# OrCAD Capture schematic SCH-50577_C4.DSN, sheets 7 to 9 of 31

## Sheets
7 05 MIMXRT1180 Part1: size C
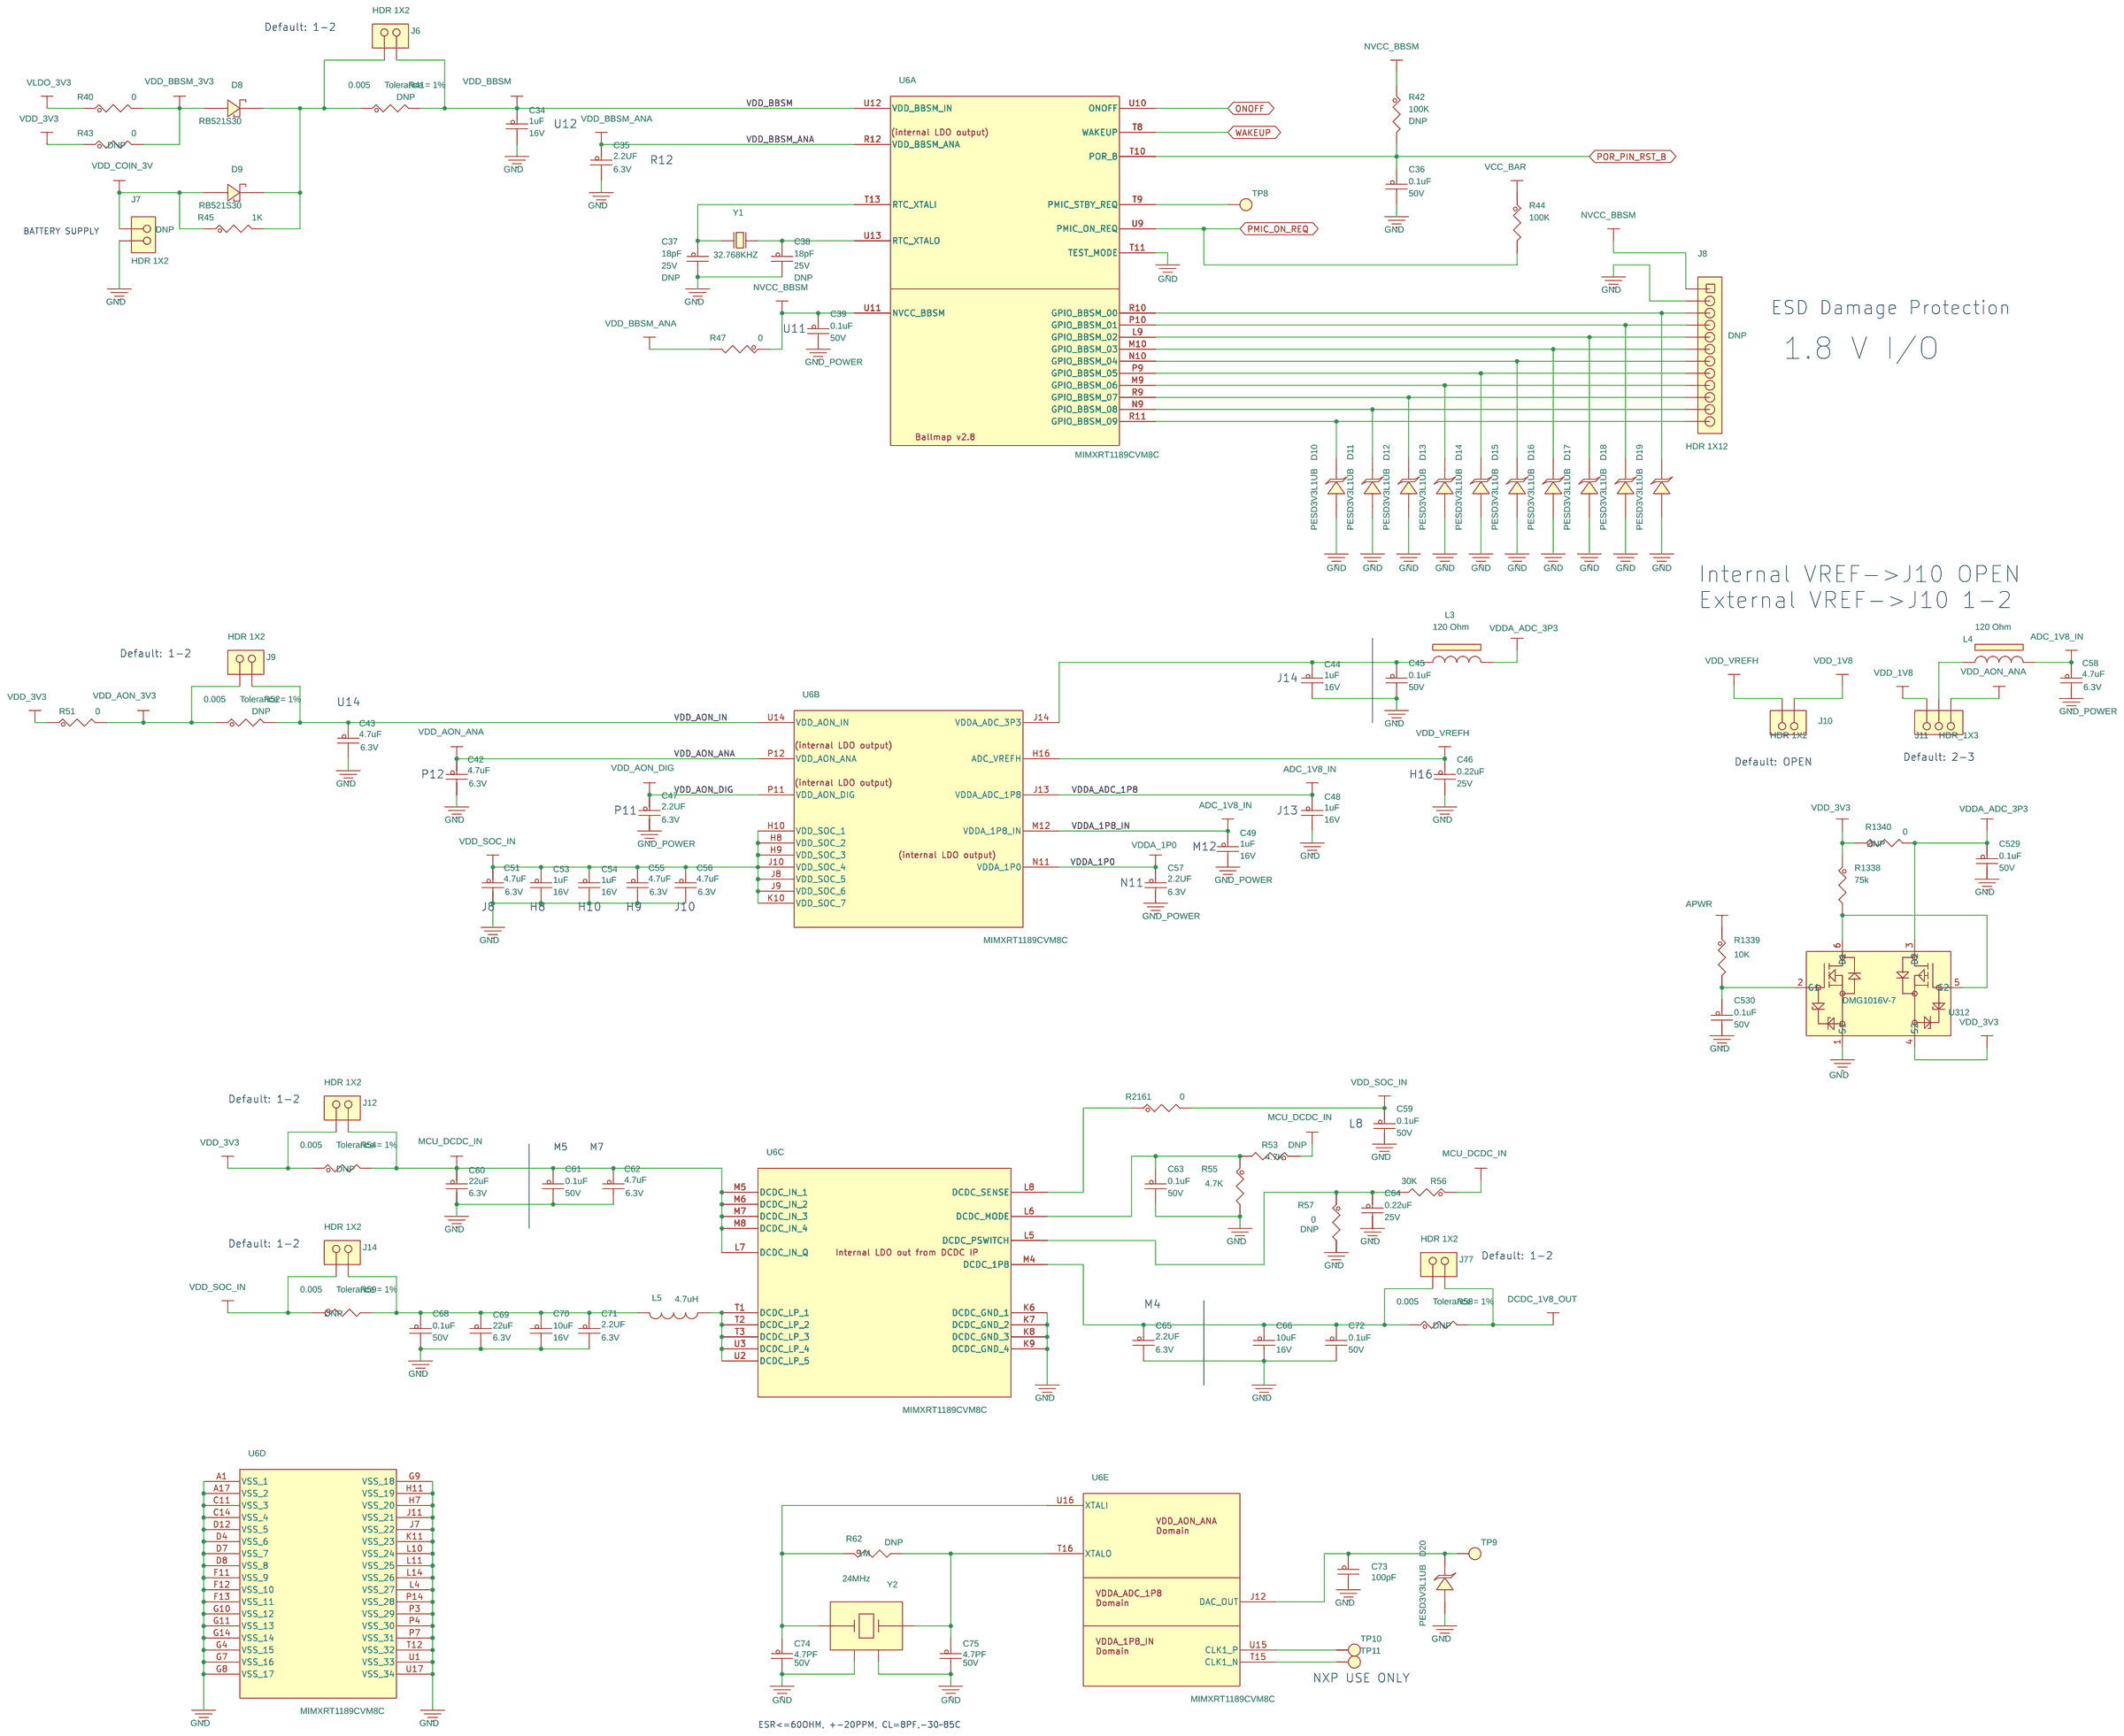
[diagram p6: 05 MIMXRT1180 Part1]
8 06 MIMXRT1180 Part2: size C
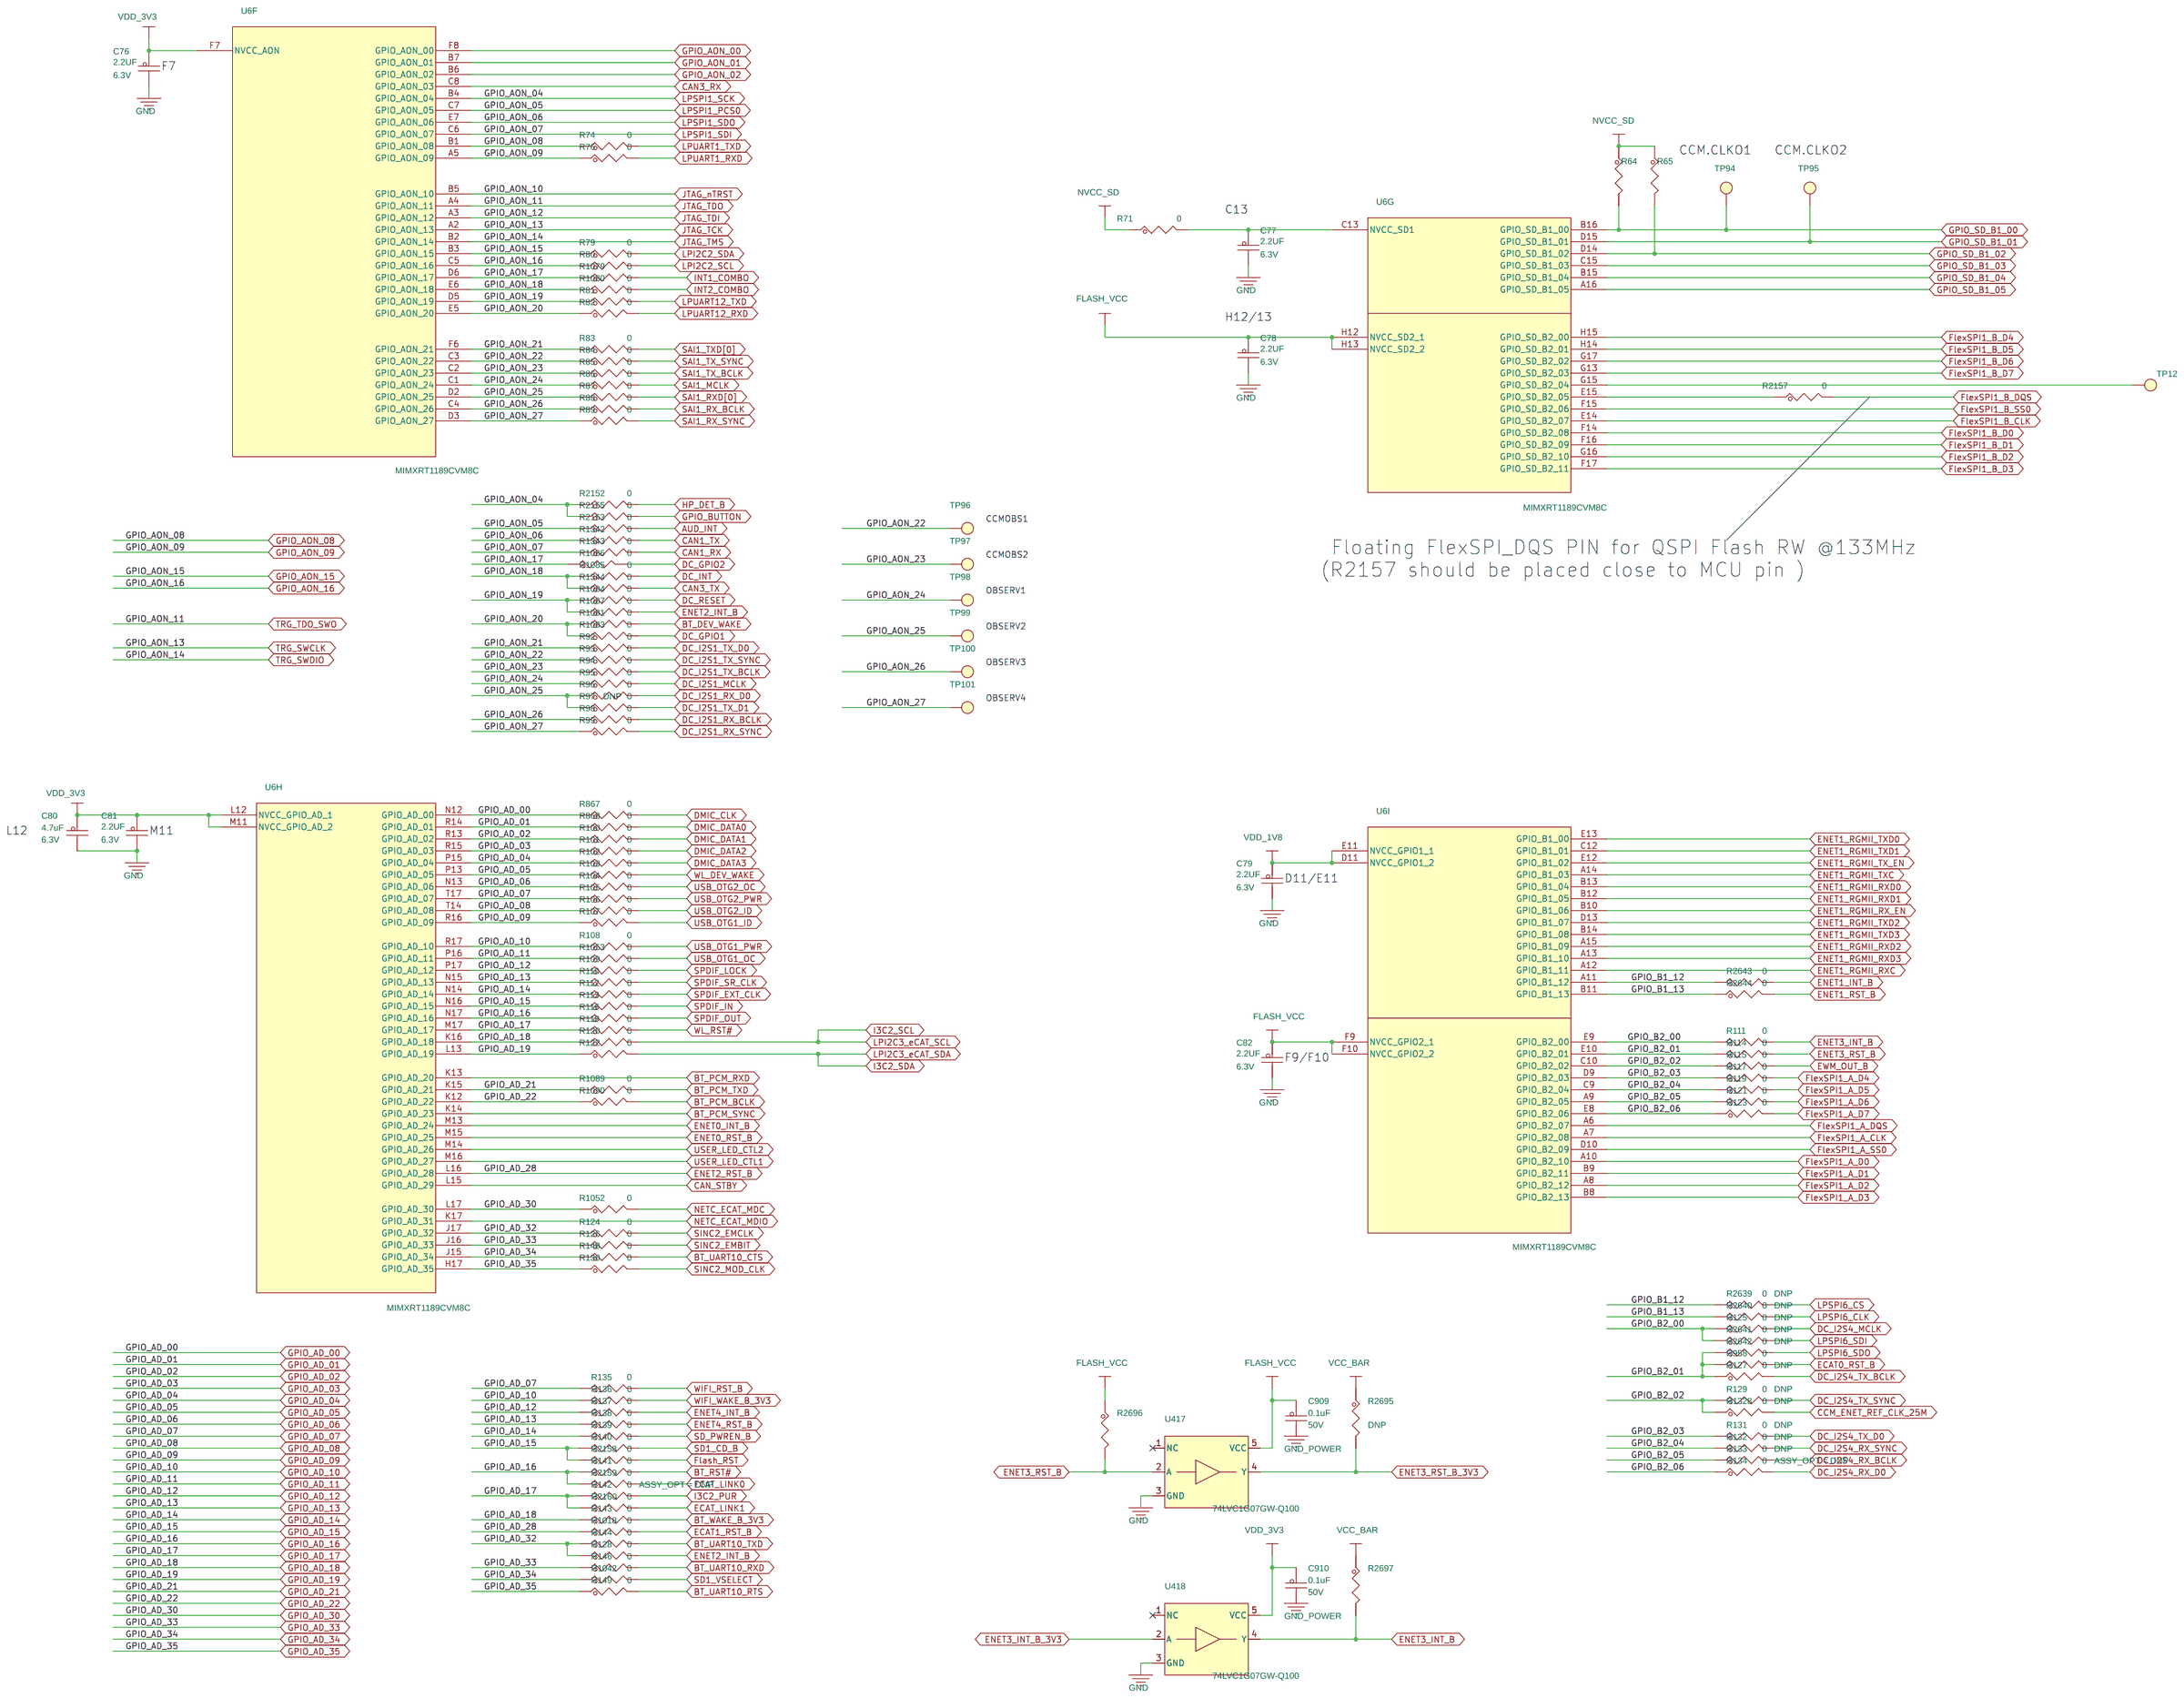
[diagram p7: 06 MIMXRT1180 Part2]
9 07 MIMXRT1180 Part3: size C
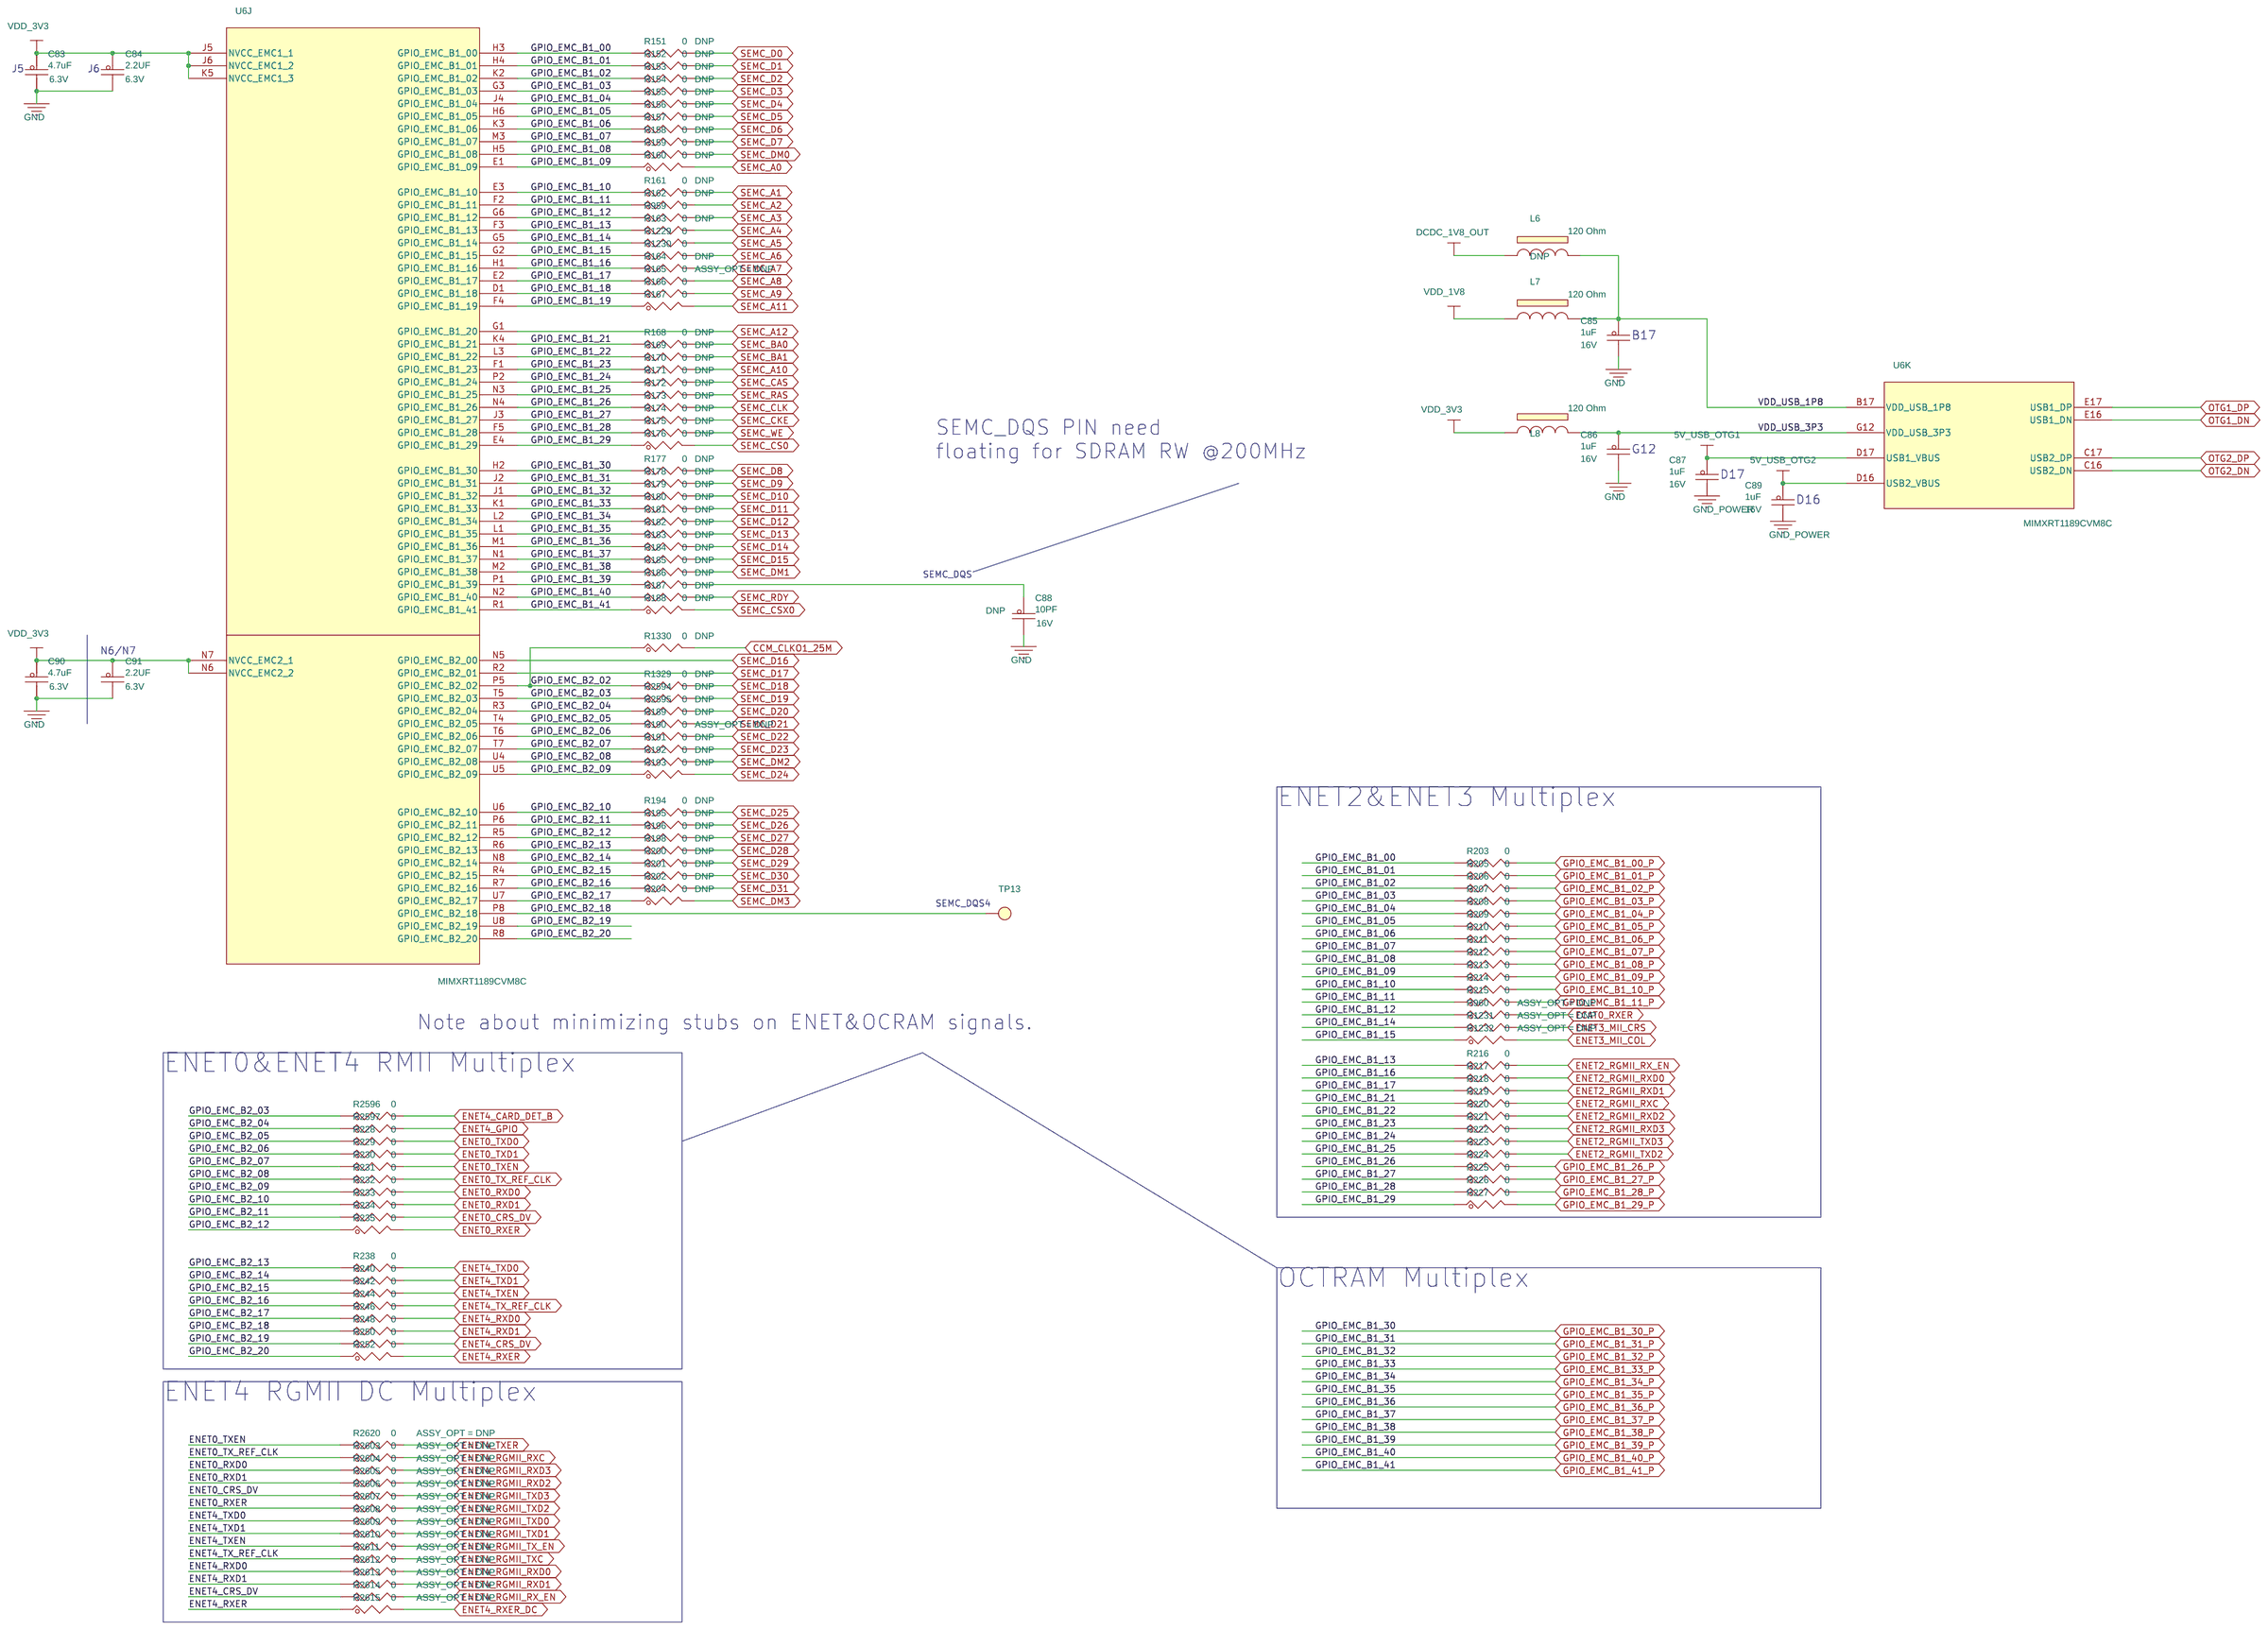
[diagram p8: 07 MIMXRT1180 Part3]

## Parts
sheet 05 MIMXRT1180 Part1
C34  1uF  [0402_CC]
C35  2.2UF  [0402_CC]
C36  0.1uF  [0402_CC]
C37  18pF  [0402_CC]
C38  18pF  [0402_CC]
C39  0.1uF  [0402_CC]
C42  4.7uF  [cc0402_tol0p15]
C43  4.7uF  [cc0402_tol0p15]
C44  1uF  [0402_CC]
C45  0.1uF  [0402_CC]
C46  0.22uF  [0402_CC]
C47  2.2UF  [0402_CC]
C48  1uF  [0402_CC]
C49  1uF  [0402_CC]
C51  4.7uF  [cc0402_tol0p15]
C53  1uF  [0402_CC]
C54  1uF  [0402_CC]
C55  4.7uF  [cc0402_tol0p15]
C56  4.7uF  [cc0402_tol0p15]
C57  2.2UF  [0402_CC]
C58  4.7uF  [cc0402_tol0p15]
C59  0.1uF  [0402_CC]
C60  22uF  [CC0603_OV]
C61  0.1uF  [0402_CC]
C62  4.7uF  [cc0402_tol0p15]
C63  0.1uF  [0402_CC]
C64  0.22uF  [0402_CC]
C65  2.2UF  [0402_CC]
C66  10uF  [CC0603_OV]
C68  0.1uF  [0402_CC]
C69  22uF  [CC0603_OV]
C70  10uF  [CC0603_OV]
C71  2.2UF  [0402_CC]
C72  0.1uF  [0402_CC]
C73  100pF  [0402_CC]
C74  4.7PF  [0402_CC]
C75  4.7PF  [0402_CC]
C529  0.1uF  [0402_CC]
C530  0.1uF  [0402_CC]
D8  RB521S30  [SOD523]
D9  RB521S30  [SOD523]
D10  PESD3V3L1UB  [sod523]
D11  PESD3V3L1UB  [sod523]
D12  PESD3V3L1UB  [sod523]
D13  PESD3V3L1UB  [sod523]
D14  PESD3V3L1UB  [sod523]
D15  PESD3V3L1UB  [sod523]
D16  PESD3V3L1UB  [sod523]
D17  PESD3V3L1UB  [sod523]
D18  PESD3V3L1UB  [sod523]
D19  PESD3V3L1UB  [sod523]
D20  PESD3V3L1UB  [sod523]
J6  HDR 1X2  [HDR102]
J7  HDR 1X2  [HDR102]
J8  HDR 1X12  [hdr112_b]
J9  HDR 1X2  [HDR102]
J10  HDR 1X2  [HDR102]
J11  HDR_1X3  [HDR103]
J12  HDR 1X2  [HDR102]
J14  HDR 1X2  [HDR102]
J77  HDR 1X2  [HDR102]
L3  120 Ohm  [0402_CC]
L4  120 Ohm  [0402_CC]
L5  4.7uH  [ind_4p2x4p2]
R40  0  [0402_CC]
R41  0.005  [RC0603_OV]
R42  100K  [0402_CC]
R43  0  [0402_CC]
R44  100K  [0402_CC]
R45  1K  [0402_CC]
R47  0  [0402_CC]
R51  0  [0402_CC]
R52  0.005  [RC0603_OV]
R53  4.7K  [0402_CC]
R54  0.005  [RC0603_OV]
R55  4.7K  [0402_CC]
R56  30K  [0402_CC]
R57  0  [0402_CC]
R58  0.005  [RC0603_OV]
R59  0.005  [RC0603_OV]
R62  1M  [0402_CC]
R1338  75k  [RC0402_25]
R1339  10K  [0402_CC]
R1340  0  [0402_CC]
R2161  0  [0402_CC]
TP8  TP_35MIL  [testpoint_35mil]
TP9  TP_35MIL  [testpoint_35mil]
TP10  TP_35MIL  [testpoint_35mil]
TP11  TP_35MIL  [testpoint_35mil]
U312  DMG1016V-7  [sot-563_6p_0p5_smt]
Y1  32.768KHZ  [XTAL2-3p2x1p5-SM]
Y2  24MHz  [xtl4_2p1x1p7mm_sm]
sheet 06 MIMXRT1180 Part2
C76  2.2UF  [0402_CC]
C77  2.2UF  [0402_CC]
C78  2.2UF  [0402_CC]
C79  2.2UF  [0402_CC]
C80  4.7uF  [cc0402_tol0p15]
C81  2.2UF  [0402_CC]
C82  2.2UF  [0402_CC]
C909  0.1uF  [0402_CC]
C910  0.1uF  [0402_CC]
R64  10K  [0402_CC]
R65  10K  [0402_CC]
R71  0  [0402_CC]
R74  0  [0402_CC]
R76  0  [0402_CC]
R79  0  [0402_CC]
R80  0  [0402_CC]
R81  0  [0402_CC]
R82  0  [0402_CC]
R83  0  [0402_CC]
R84  0  [0402_CC]
R85  0  [0402_CC]
R86  0  [0402_CC]
R87  0  [0402_CC]
R88  0  [0402_CC]
R89  0  [0402_CC]
R92  0  [0402_CC]
R93  0  [0402_CC]
R94  0  [0402_CC]
R95  0  [0402_CC]
R96  0  [0402_CC]
R97  0  [0402_CC]
R98  0  [0402_CC]
R99  0  [0402_CC]
R100  0  [0402_CC]
R101  0  [0402_CC]
R102  0  [0402_CC]
R103  0  [0402_CC]
R104  0  [0402_CC]
R105  0  [0402_CC]
R106  0  [0402_CC]
R107  0  [0402_CC]
R108  0  [0402_CC]
R109  0  [0402_CC]
R110  0  [0402_CC]
R111  0  [0402_CC]
R112  0  [0402_CC]
R113  0  [0402_CC]
R114  0  [0402_CC]
R115  0  [0402_CC]
R116  0  [0402_CC]
R117  0  [0402_CC]
R118  0  [0402_CC]
R119  0  [0402_CC]
R120  0  [0402_CC]
R121  0  [0402_CC]
R122  0  [0402_CC]
R123  0  [0402_CC]
R124  0  [0402_CC]
R125  0  [0402_CC]
R126  0  [0402_CC]
R127  0  [0402_CC]
R128  0  [0402_CC]
R129  0  [0402_CC]
R130  0  [0402_CC]
R131  0  [0402_CC]
R132  0  [0402_CC]
R133  0  [0402_CC]
R134  0  [0402_CC]
R135  0  [0402_CC]
R136  0  [0402_CC]
R137  0  [0402_CC]
R138  0  [0402_CC]
R139  0  [0402_CC]
R140  0  [0402_CC]
R141  0  [0402_CC]
R142  0  [0402_CC]
R143  0  [0402_CC]
R144  0  [0402_CC]
R146  0  [0402_CC]
R148  0  [0402_CC]
R149  0  [0402_CC]
R867  0  [0402_CC]
R868  0  [0402_CC]
R958  0  [0402_CC]
R1018  0  [0402_CC]
R1042  0  [0402_CC]
R1052  0  [0402_CC]
R1053  0  [0402_CC]
R1079  0  [0402_CC]
R1080  0  [0402_CC]
R1081  0  [0402_CC]
R1083  0  [0402_CC]
R1084  0  [0402_CC]
R1085  0  [0402_CC]
R1086  0  [0402_CC]
R1087  0  [0402_CC]
R1089  0  [0402_CC]
R1090  0  [0402_CC]
R1328  0  [0402_CC]
R1342  0  [0402_CC]
R1343  0  [0402_CC]
R1344  0  [0402_CC]
R2152  0  [0402_CC]
R2153  0  [0402_CC]
R2155  0  [0402_CC]
R2157  0  [0402_CC]
R2158  0  [0402_CC]
R2159  0  [0402_CC]
R2160  0  [0402_CC]
R2639  0  [0402_CC]
R2640  0  [0402_CC]
R2641  0  [0402_CC]
R2642  0  [0402_CC]
R2643  0  [0402_CC]
R2644  0  [0402_CC]
R2695  4.7K  [0402_CC]
R2696  10K  [0402_CC]
R2697  4.7K  [0402_CC]
TP12  TP_35MIL  [testpoint_35mil]
TP94  TP_35MIL  [testpoint_35mil]
TP95  TP_35MIL  [testpoint_35mil]
TP96  TP_35MIL  [testpoint_35mil]
TP97  TP_35MIL  [testpoint_35mil]
TP98  TP_35MIL  [testpoint_35mil]
TP99  TP_35MIL  [testpoint_35mil]
TP100  TP_35MIL  [testpoint_35mil]
TP101  TP_35MIL  [testpoint_35mil]
U417  74LVC1G07GW-Q100  [sc70-5]
U418  74LVC1G07GW-Q100  [sc70-5]
sheet 07 MIMXRT1180 Part3
C83  4.7uF  [cc0402_tol0p15]
C84  2.2UF  [0402_CC]
C85  1uF  [0402_CC]
C86  1uF  [0402_CC]
C87  1uF  [0402_CC]
C88  10PF  [0402_CC]
C89  1uF  [0402_CC]
C90  4.7uF  [cc0402_tol0p15]
C91  2.2UF  [0402_CC]
L6  120 Ohm  [0402_CC]
L7  120 Ohm  [0402_CC]
L8  120 Ohm  [0402_CC]
R151  0  [0402_CC]
R152  0  [0402_CC]
R153  0  [0402_CC]
R154  0  [0402_CC]
R155  0  [0402_CC]
R156  0  [0402_CC]
R157  0  [0402_CC]
R158  0  [0402_CC]
R159  0  [0402_CC]
R160  0  [0402_CC]
R161  0  [0402_CC]
R162  0  [0402_CC]
R163  0  [0402_CC]
R164  0  [0402_CC]
R165  0  [0402_CC]
R166  0  [0402_CC]
R167  0  [0402_CC]
R168  0  [0402_CC]
R169  0  [0402_CC]
R170  0  [0402_CC]
R171  0  [0402_CC]
R172  0  [0402_CC]
R173  0  [0402_CC]
R174  0  [0402_CC]
R175  0  [0402_CC]
R176  0  [0402_CC]
R177  0  [0402_CC]
R178  0  [0402_CC]
R179  0  [0402_CC]
R180  0  [0402_CC]
R181  0  [0402_CC]
R182  0  [0402_CC]
R183  0  [0402_CC]
R184  0  [0402_CC]
R185  0  [0402_CC]
R186  0  [0402_CC]
R187  0  [0402_CC]
R188  0  [0402_CC]
R189  0  [0402_CC]
R190  0  [0402_CC]
R191  0  [0402_CC]
R192  0  [0402_CC]
R193  0  [0402_CC]
R194  0  [0402_CC]
R195  0  [0402_CC]
R196  0  [0402_CC]
R198  0  [0402_CC]
R200  0  [0402_CC]
R201  0  [0402_CC]
R202  0  [0402_CC]
R203  0  [0402_CC]
R204  0  [0402_CC]
R205  0  [0402_CC]
R206  0  [0402_CC]
R207  0  [0402_CC]
R208  0  [0402_CC]
R209  0  [0402_CC]
R210  0  [0402_CC]
R211  0  [0402_CC]
R212  0  [0402_CC]
R213  0  [0402_CC]
R214  0  [0402_CC]
R215  0  [0402_CC]
R216  0  [0402_CC]
R217  0  [0402_CC]
R218  0  [0402_CC]
R219  0  [0402_CC]
R220  0  [0402_CC]
R221  0  [0402_CC]
R222  0  [0402_CC]
R223  0  [0402_CC]
R224  0  [0402_CC]
R225  0  [0402_CC]
R226  0  [0402_CC]
R227  0  [0402_CC]
R228  0  [0402_CC]
R229  0  [0402_CC]
R230  0  [0402_CC]
R231  0  [0402_CC]
R232  0  [0402_CC]
R233  0  [0402_CC]
R234  0  [0402_CC]
R235  0  [0402_CC]
R238  0  [0402_CC]
R240  0  [0402_CC]
R242  0  [0402_CC]
R244  0  [0402_CC]
R246  0  [0402_CC]
R248  0  [0402_CC]
R250  0  [0402_CC]
R252  0  [0402_CC]
R959  0  [0402_CC]
R960  0  [0402_CC]
R1229  0  [0402_CC]
R1230  0  [0402_CC]
R1231  0  [0402_CC]
R1232  0  [0402_CC]
R1329  0  [0402_CC]
R1330  0  [0402_CC]
R2594  0  [0402_CC]
R2595  0  [0402_CC]
R2596  0  [0402_CC]
R2597  0  [0402_CC]
R2603  0  [0402_CC]
R2604  0  [0402_CC]
R2605  0  [0402_CC]
R2606  0  [0402_CC]
R2607  0  [0402_CC]
R2608  0  [0402_CC]
R2609  0  [0402_CC]
R2610  0  [0402_CC]
R2611  0  [0402_CC]
R2612  0  [0402_CC]
R2613  0  [0402_CC]
R2614  0  [0402_CC]
R2615  0  [0402_CC]
R2620  0  [0402_CC]
TP13  TP_35MIL  [testpoint_35mil]
U6  MIMXRT1189CVM8C  [bga289_0p8_14x14_1p52mm]  (sections A,B,C,D,E,F,G,H,I,J,K)

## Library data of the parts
C34 C44 C48 C49 C53 C54 C85-C87 C89 = CAP_NP: CAP CER 1.0uF 16V 10% X6S 0402; AGILE_PN: 150-80262; CAD_APPROVED: Yes; FPLIST: CC0402_25,CC0402_HD,0402_CC,capc0402_l; HEIGHT: 0.55MM; MFG_NAME01: MURATA; MFG_PN01: GRM155C81C105KE11D; ROHS: Yes; Temp Range: -55°C to +105°C; Tolerance: 10%; VOLTAGE: 16V
C35 C47 C57 C65 C71 C76-C79 C81 C82 C84 C91 = CAP_NP: CAP CER 2.2UF 6.3V 10% X6S 0402; AGILE_PN: 150-80139; CAD_APPROVED: Yes; FPLIST: CC0402_25,CC0402_HD,0402_CC,capc0402_l; HEIGHT: 0.55MM; MFG_NAME01: MURATA; MFG_PN01: GRM155C80J225KE95D; ROHS: Yes; Temp Range: -55 to 105&#8451;; VOLTAGE: 6.3V
C36 C39 C45 C59 C61 C63 C68 C72 C529 C530 C909 C910 = CAP_NP: CAP CER 0.1uF 50V 10% X7R AEC-Q200 0402; AGILE_PN: 150-79461; CAD_APPROVED: Yes; FPLIST: CC0402_25,CC0402_HD,0402_CC,CC0402_18,capc0402_l; HEIGHT: 0.55MM; MFG_NAME01: MURATA; MFG_PN01: GCM155R71H104KE02D; Package Size: 0402; ROHS: Yes; Tolerance: 10%; VOLTAGE: 50V
C37 C38 = CAP_NP: CAP CER 18pF 25V 5% C0G 0402; AGILE_PN: 150-78760; ASSY_OPT: DNP; CAD_APPROVED: Yes; FPLIST: CC0402_25,CC0402_HD,0402_CC; HEIGHT: 0.56MM; MFG_NAME01: AVX; MFG_PN01: 04023A180JAT2A; ROHS: Yes; TOL: 5%; Tolerance: 5%; VOLTAGE: 25V
C42 C43 C51 C55 C56 C58 C62 C80 C83 C90 = CAP_NP: CAP CER 4.7uF 6.3V 20% X6S 0402; AGILE_PN: 150-81296; CAD_APPROVED: Yes; FPLIST: cc0402_tol0p15,cc0402_tol0p15_ov,cc0402_25_tol0p2,0402_cc_nsp; HEIGHT: 0.65MM; MFG_NAME01: MURATA; MFG_PN01: GRM155C80J475MEAA; Package Size: 0402 (1005 Metric); Package Type: SMD/SMT; ROHS: Yes; Rated Voltage: 6.3V; Temp Range: -55°C to +105°C; Tolerance: 20%; VOLTAGE: 6.3V
C46 C64 = CAP_NP: CAP CER 0.22uF 25V 10% X6S AEC-Q200 0402; AGILE_PN: 150-79689; CAD_APPROVED: Yes; FPLIST: CC0402_25,CC0402_HD,0402_CC,capc0402_l; HEIGHT: 0.55MM; MFG_NAME01: MURATA; MFG_PN01: GRT155C81E224KE01; Package Size: 0402; ROHS: Yes; Tolerance: 10%; VOLTAGE: 25V
C60 C69 = CAP_NP: CAP CER 22uF 6.3V 20% X6S 0603; AGILE_PN: 150-79717; CAD_APPROVED: Yes; FPLIST: CC0603_OV,CC0603,0603_CC_NSP; HEIGHT: 1MM; MFG_NAME01: MURATA; MFG_PN01: GRM188C80J226ME15D; Package Size: 0603; Package Type: 180mm ReelPAPER W8P4; ROHS: Yes; Tolerance: 20%; VOLTAGE: 6.3V
C66 C70 = CAP_NP: CAP CER 10uF 16V 20% X6S AEC-Q200 0603; AGILE_PN: 150-80530; CAD_APPROVED: Yes; FPLIST: CC0603_OV,CC0603,0603_CC_NSP; HEIGHT: 1MM; MFG_NAME01: MURATA; MFG_PN01: GRT188C81C106ME13D; Package Size: 0603; ROHS: Yes; Temp Range: -55°C to 105°C; Tolerance: 10%; VOLTAGE: 16V
C73 = CAP_NP: CAP CER 100pF 50V 5% C0G AEC-Q200 0402; AGILE_PN: 150-79021; CAD_APPROVED: Yes; FPLIST: CC0402_25,CC0402_HD,0402_CC,capc0402_l; HEIGHT: 0.55MM; MFG_NAME01: MURATA; MFG_PN01: GCM1555C1H101JA16B; Package Size: 0402; Package Type: Bulk Bag; ROHS: Yes; Tolerance: 5%; VOLTAGE: 50V
C74 C75 = CAP_NP: CAP CER 4.7PF 50V 0.25PF C0G 0402; AGILE_PN: 150-76335; CAD_APPROVED: Yes; FPLIST: CC0402_25,CC0402_HD,0402_CC; HEIGHT: 0.56MM; MFG_NAME01: AVX; MFG_PN01: 04025A4R7CAT2A; ROHS: Yes; Tolerance: 0.25pF; VOLTAGE: 50V
D8 D9 = DIODE_SCHTKY: DIODE SCH RECT 200MA 30V AEC-Q101 SOD-523; AGILE_PN: 480-79672; CAD_APPROVED: Yes; HEIGHT: 0.65MM; MFG_NAME01: NEXPERIA; MFG_PN01: RB521S30,115; ROHS: Yes; VOLTAGE: 30V
D10-D20 = DIODE_TVS: DIODE TVS UNIDIR 3.3V 11V 4.5A AEC-Q101 SOD523; AGILE_PN: 480-80332; CAD_APPROVED: YES; HEIGHT: 0.65MM; MFG_NAME01: Nexperia; MFG_PN01: PESD3V3L1UB,115; Package Size: SC-79, SOD-523; Rated Power: 45W; Temp Range: -55°C to +150°C
J6 J9 J12 J14 J77 = CONN_HDR_2X1: HDR 1X2 TH 100MIL SP 339H AU 98L; AGILE_PN: 210-81490; CAD_APPROVED: Yes; HEIGHT: 8.59MM; Jumper(Default): 1-2; MFG_NAME01: ANYTRONIC CORPORATION LIMITED; MFG_PN01: 0901S0202011N9T-31RF; ROHS: Yes; Temp_Range: -55°C to +105°C
J7 = CONN_HDR_2X1: HDR 1X2 TH 100MIL SP 339H AU 98L; AGILE_PN: 210-81490; ASSY_OPT: DNP; CAD_APPROVED: Yes; HEIGHT: 8.59MM; MFG_NAME01: ANYTRONIC CORPORATION LIMITED; MFG_PN01: 0901S0202011N9T-31RF; ROHS: Yes; Temp Range: -55°C to +105°C; Temp_Range: -55°C to +105°C
J8 = HDR-1X12: HDR 1X12 TH 100MIL SP 344H AU 118L; 3D_Mechanical_Footprint_File: ftp://fcl.am.freescale.net/ALLEGRO/step/hdr112_b.STEP; AGILE_PN: 210-81940; ASSY_OPT: DNP; CAD_APPROVED: Yes; HEIGHT: 8.74MM; MFG_NAME01: WURTH ELEKTRONIK EISOS GMBH & CO. KG (ELECTRONIC & ELECTROMEHANICAL COMP); MFG_PN01: 61301211121; Package Size: 2.54x30.48mm; ROHS: Yes; Temp Range: -40°C ~ 105°C; Temp_Range: -40°C ~ 105°C
J10 = CONN_HDR_2X1: HDR 1X2 TH 100MIL SP 339H AU 98L; AGILE_PN: 210-81490; CAD_APPROVED: Yes; HEIGHT: 8.59MM; MFG_NAME01: ANYTRONIC CORPORATION LIMITED; MFG_PN01: 0901S0202011N9T-31RF; ROHS: Yes; Temp Range: -55°C to +105°C; Temp_Range: -55°C to +105°C
J11 = CONN_HDR_3X1: HDR 1X3 TH 100MIL SP 338H AU 98L; 3D_Mechanical_Footprint_File: ftp://fcl.am.freescale.net/ALLEGRO/step/hdr103_330h.STEP; AGILE_PN: 210-81491; CAD_APPROVED: Yes; HEIGHT: 8.59MM; Jumper(Default): 2-3; MFG_NAME01: ANYTRONIC CORPORATION LIMITED; MFG_PN01: 0901S0203011N9T-31RF; ROHS: Yes; Temp Range: -55°C to +105°C; Temp_Range: -55°C to +105°C
L3 L4 L7 L8 = INDUCTOR_FERRITE: IND FER BEAD 120 OHM@100MHZ 0.5A 25% 0402; AGILE_PN: 180-77771; CAD_APPROVED: Yes; FPLIST: IND_0402,0402_CC; HEIGHT: 0.55MM; MFG_NAME01: MURATA; MFG_PN01: BLM15AG121SN1D; PART_TYPE: FERRITE\BEAD; Package Size: 0402; ROHS: Yes; Tolerance: 25%
L5 = INDUCTOR: IND PWR 4.7uH@100kHz 1.55A 20% SMT; AGILE_PN: 180-78685; CAD_APPROVED: Yes; HEIGHT: 1.2MM; MFG_NAME01: WURTH ELEKTRONIK EISOS GMBH & CO. KG (ELECTRONIC & ELECTROMEHANICAL COMP); MFG_PN01: 74404041047; PART_TYPE: INDUCTOR\POWER; ROHS: Yes; Temp Range: -40C to +125C; Temp_Range: -40C to +125C; Tolerance: 20%
R40 R47 R51 R71 R166 R167 R203 R205-R235 R238 R240 R242 R244 R246 R248 R250 R252 R867 R868 R959 R1229 R1230 R2157 R2161 R2596 R2597 = RES: RES MF ZERO OHM 1/16W 5% 0402; AGILE_PN: 470-75394; CAD_APPROVED: Yes; FPLIST: RC0402_25,RC0402_HD,RC0402_X2,0402_CC; HEIGHT: 0.45 MM; MFG_NAME01: ROHM; MFG_PN01: MCR01MZPJ000; ROHS: Yes; Tolerance: 5%; VOLTAGE: 1/16W
R41 R52 R54 R58 R59 = RES: RES MF 0.005 OHM 1/4W 1% 0603; AGILE_PN: 470-82340; ASSY_OPT: DNP; CAD_APPROVED: Yes; FPLIST: RC0603_OV,RC0603,0603_CC; HEIGHT: 0.65MM; MFG_NAME01: PANASONIC; MFG_PN01: ERJ-3LWFR005V; ROHS: Yes; Temp Range: -55C to 125C; Temp_Range: -55C to 125C; Tolerance: 1%
R42 = RES: RES MF 100K 1/16W 5% 0402; AGILE_PN: 470-75597; ASSY_OPT: DNP; CAD_APPROVED: Yes; FPLIST: RC0402_25,RC0402_HD,0402_CC; HEIGHT: 0.40 MM; MFG_NAME01: VENKEL COMPANY; MFG_PN01: CR0402-16W-104JT; ROHS: Yes; Temp Range: -55C to +155C; Temp_Range: -55C to +155C; Tolerance: 5%; VOLTAGE: 50V
R43 R57 R151-R165 R168-R196 R198 R200-R202 R204 R960 R1231 R1232 R1329 R1330 R1340 R2594 R2595 R2603-R2615 R2620 = RES: RES MF ZERO OHM 1/16W 5% 0402; AGILE_PN: 470-75394; ASSY_OPT: DNP; CAD_APPROVED: Yes; FPLIST: RC0402_25,RC0402_HD,RC0402_X2,0402_CC; HEIGHT: 0.45 MM; MFG_NAME01: ROHM; MFG_PN01: MCR01MZPJ000; ROHS: Yes; Tolerance: 5%; VOLTAGE: 1/16W
R44 = RES: RES MF 100K 1/16W 5% 0402; AGILE_PN: 470-75597; CAD_APPROVED: Yes; FPLIST: RC0402_25,RC0402_HD,0402_CC; HEIGHT: 0.40 MM; MFG_NAME01: VENKEL COMPANY; MFG_PN01: CR0402-16W-104JT; ROHS: Yes; Temp Range: -55C to +155C; Temp_Range: -55C to +155C; Tolerance: 5%; VOLTAGE: 50V
R45 = RES: RES MF 1.0K 1/16W 5% 0402; AGILE_PN: 470-75555; CAD_APPROVED: Yes; FPLIST: RC0402_25,RC0402_HD,RC0402_X2,0402_CC; HEIGHT: 0.41mm; MFG_NAME01: VISHAY INTERTECHNOLOGY; MFG_PN01: CRCW04021K00JNED; ROHS: Yes; Tolerance: 5%
R53 = RES: RES MF 4.7K 1/16W 5% 0402; AGILE_PN: 470-75626; ASSY_OPT: DNP; CAD_APPROVED: Yes; FPLIST: RC0402_25,RC0402_HD,0402_CC; HEIGHT: 0.41mm; MFG_NAME01: NIC COMPONENTS CORP; MFG_PN01: NRCL04J472TRF; ROHS: Yes; Tolerance: 5%
R55 = RES: RES MF 4.7K 1/16W 5% 0402; AGILE_PN: 470-75626; CAD_APPROVED: Yes; FPLIST: RC0402_25,RC0402_HD,0402_CC; HEIGHT: 0.41mm; MFG_NAME01: NIC COMPONENTS CORP; MFG_PN01: NRCL04J472TRF; ROHS: Yes; Tolerance: 5%
R56 = RES: RES MF 30K 1/16W 1% 0402; AGILE_PN: 470-76590; CAD_APPROVED: Yes; FPLIST: RC0402_25,RC0402_HD,0402_CC; HEIGHT: 0.4MM; MFG_NAME01: THYE MING TECH CO LTD; MFG_PN01: CR02FL6-30K; ROHS: Yes; Tolerance: 1%; VOLTAGE: 50V
R62 = RES: RES MF 1M 1/10W 5% AEC-Q200 0402; AGILE_PN: 470-79978; ASSY_OPT: DNP; CAD_APPROVED: Yes; FPLIST: RC0402_25,RC0402_HD,0402_CC; HEIGHT: 0.4MM; MFG_NAME01: KOA SPEER; MFG_PN01: RK73B1ETTP105J; ROHS: Yes; Temp Range: -55&#8451; to 155&#8451;; Temp_Range: -55&#8451; to 155&#8451;; Tolerance: 5%; VOLTAGE: 50V
R1338 = RES: RES MF 75k Ohm 1/16W 1% AEC-Q200 0402; AGILE_PN: 470-80500; CAD_APPROVED: Yes; FPLIST: RC0402_25,RC0402_HD,0402_CC; HEIGHT: 0.4 MM; MFG_NAME01: VISHAY INTERTECHNOLOGY; MFG_PN01: CRCW040275K0FKED; ROHS: Yes; Tolerance: 1%
R1339 = RES: RES MF 10K 1/16W 5% 0402; AGILE_PN: 470-75557; CAD_APPROVED: Yes; FPLIST: RC0402_25,RC0402_HD,0402_CC; HEIGHT: 0.4 MM; MFG_NAME01: VISHAY INTERTECHNOLOGY; MFG_PN01: CRCW040210K0JNED; ROHS: Yes; Tolerance: 5%
TP8-TP13 TP94-TP101 = T_POINT_R: TEST POINT PAD .035 SMT, no part to order; AGILE_PN: 510-75618; CAD_APPROVED: Yes; HEIGHT: 0.1MM; ROHS: Yes
U312 = NX3008_SOT666_6PIN: TRAN N/PMOS DUAL 20V AEC-Q101 SOT-563; AGILE_PN: 480-79913; CAD_APPROVED: Yes; HEIGHT: 0.6MM; MFG_NAME01: DIODES INC; ROHS: Yes; Temp Range: -55oC ~ +150oC
Y1 = CRYSTAL: XTAL 32.768KHZ 7PF 20PPM -- SMT; AGILE_PN: 230-78102; CAD_APPROVED: Yes; HEIGHT: 0.9MM; MFG_NAME01: EPSON ELECTRONICS; MFG_PN01: FC-135 32.7680KA-AG3; ROHS: Yes
Y2 = XTAL_13: XTAL 24MHz -- 20PPM 8pF SMT; AGILE_PN: 230-78313; CAD_APPROVED: Yes; HEIGHT: 0.7MM; MFG_NAME01: MURATA; MFG_PN01: XRCGB24M000F2P91R0; ROHS: Yes
R64 R65 R2696 = RES: RES MF 10K 1/16W 5% 0402; AGILE_PN: 470-75557; CAD_APPROVED: Yes; FPLIST: RC0402_25,RC0402_HD,0402_CC; HEIGHT: 0.4 MM; MFG_NAME01: VISHAY INTERTECHNOLOGY; MFG_PN01: CRCW040210K0JNED; ROHS: Yes; TOL: 5%; Tolerance: 5%
R74 R76 R79-R89 R92-R96 R98-R124 R126 R128 R130 R135-R141 R143 R144 R146 R148 R149 R958 R1018 R1042 R1052 R1053 R1079-R1081 R1083-R1087 R1089 R1090 R1342-R1344 R2152 R2153 R2155 R2158-R2160 R2643 R2644 = RES: RES MF ZERO OHM 1/16W 5% 0402; AGILE_PN: 470-75394; CAD_APPROVED: Yes; FPLIST: RC0402_25,RC0402_HD,RC0402_X2,0402_CC; HEIGHT: 0.45 MM; MFG_NAME01: YAGEO AMERICA; MFG_PN01: RC0402JR-070RL; ROHS: Yes; Tolerance: 5%; VOLTAGE: 1/16W
R97 R125 R127 R129 R131-R134 R142 R1328 R2639-R2642 = RES: RES MF ZERO OHM 1/16W 5% 0402; AGILE_PN: 470-75394; ASSY_OPT: DNP; CAD_APPROVED: Yes; FPLIST: RC0402_25,RC0402_HD,RC0402_X2,0402_CC; HEIGHT: 0.45 MM; MFG_NAME01: YAGEO AMERICA; MFG_PN01: RC0402JR-070RL; ROHS: Yes; Tolerance: 5%; VOLTAGE: 1/16W
R2695 = RES: RES MF 4.70K 1/16W 1% 0402; AGILE_PN: 470-75418; ASSY_OPT: DNP; CAD_APPROVED: Yes; FPLIST: RC0402_25,RC0402_HD,0402_CC; HEIGHT: 0.4mm; MFG_NAME01: WALSIN TECHNOLOGY CORP.; MFG_PN01: WR04X4701FTL; ROHS: Yes; TOL: 1%; Tolerance: 1%; VOLTAGE: 1/16W
R2697 = RES: RES MF 4.70K 1/16W 1% 0402; AGILE_PN: 470-75418; CAD_APPROVED: Yes; FPLIST: RC0402_25,RC0402_HD,0402_CC; HEIGHT: 0.4mm; MFG_NAME01: WALSIN TECHNOLOGY CORP.; MFG_PN01: WR04X4701FTL; ROHS: Yes; Tolerance: 1%; VOLTAGE: 1/16W
U417 U418 = 74AUP1G07GW: IC BUF NON-INV SGL 1.65-5.5V AEC-Q100 TSSOP5; 3D_Mechanical_Footprint_File: ftp://fcl.am.freescale.net/ALLEGRO/step/sc70-5.STEP; AGILE_PN: 312-82179; CAD_APPROVED: Yes; HEIGHT: 1.1MM; MFG_NAME01: NEXPERIA; MFG_PN01: 74LVC1G07GW-Q100H; ROHS: Yes; Temp Range: -40 to +125C; VOLTAGE: 1.65-5.5V
C88 = CAP_NP: CAP CER 10PF 16V 0.25PF C0G 0402; AGILE_PN: 150-75722; ASSY_OPT: DNP; CAD_APPROVED: Yes; FPLIST: CC0402_25,CC0402_HD,0402_CC; HEIGHT: 0.56MM; MFG_NAME01: SAMSUNG; MFG_PN01: CL05C100CO5NNNC; Package Size: 0402; Package Type: Paper 7; ROHS: Yes; Tolerance: 0.25PF; VOLTAGE: 16V
L6 = INDUCTOR_FERRITE: IND FER BEAD 120 OHM@100MHZ 0.5A 25% 0402; AGILE_PN: 180-77771; ASSY_OPT: DNP; CAD_APPROVED: Yes; FPLIST: IND_0402,0402_CC; HEIGHT: 0.55MM; MFG_NAME01: MURATA; MFG_PN01: BLM15AG121SN1D; PART_TYPE: FERRITE\BEAD; Package Size: 0402; ROHS: Yes; Tolerance: 25%
U6 = RT1180-BGA289: IC CPU iMX RT1180 800MHz BGA289; 3D_Mechanical_Footprint_File: http://fcl.am.freescale.net/ALLEGRO/step/bga289_0p8_14x14_1p52mm.step; AGILE_PN: TMP-CIP-19750; CAD_APPROVED: Yes; HEIGHT: 1.52mm; MFG_NAME01: NXP SEMICONDUCTORS; PRE_APN: 330-10027; ROHS: Yes

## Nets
5V_USB_OTG1: C87.1 U6.D17(USB1_VBUS) ; also on sheet 5 19
5V_USB_OTG2: C89.1 U6.D16(USB2_VBUS) ; also on sheet 5 19
GND: C34.2 C35.2 C36.2 C37.2 C38.2 C39.2 C42.2 C43.2 C44.2 C45.2 C46.2 C47.2 C48.2 C49.2 C51.2 C53.2 C54.2 C55.2 C56.2 C57.2 C58.2 C59.2 C60.2 C61.2 C62.2 C63.2 C64.2 C65.2 C66.2 C68.2 C69.2 C70.2 C71.2 C72.2 C73.2 C74.2 C75.2 C76.2 C77.2 C78.2 C79.2 C80.2 C81.2 C82.2 C83.2 C84.2 C85.2 C86.2 C87.2 C88.2 C89.2 C90.2 C91.2 C529.2 C530.2 C909.2 C910.2 D10.A D11.A D12.A D13.A D14.A D15.A D16.A D17.A D18.A D19.A D20.A J7.2 J8.2 R55.2 R57.2 U6.A1(VSS_1) U6.A17(VSS_2) U6.C11(VSS_3) U6.C14(VSS_4) U6.D4(VSS_6) U6.D7(VSS_7) U6.D8(VSS_8) U6.D12(VSS_5) U6.F11(VSS_9) U6.F12(VSS_10) U6.F13(VSS_11) U6.G4(VSS_15) U6.G7(VSS_16) U6.G8(VSS_17) U6.G9(VSS_18) U6.G10(VSS_12) U6.G11(VSS_13) U6.G14(VSS_14) U6.H7(VSS_20) U6.H11(VSS_19) U6.J7(VSS_22) U6.J11(VSS_21) U6.K6(DCDC_GND_1) U6.K7(DCDC_GND_2) U6.K8(DCDC_GND_3) U6.K9(DCDC_GND_4) U6.K11(VSS_23) U6.L4(VSS_27) U6.L10(VSS_24) U6.L11(VSS_25) U6.L14(VSS_26) U6.P3(VSS_29) U6.P4(VSS_30) U6.P7(VSS_31) U6.P14(VSS_28) U6.T11(TEST_MODE) U6.T12(VSS_32) U6.U1(VSS_33) U6.U17(VSS_34) U312.1(S1) U417.3(GND) U418.3(GND) Y2.2 Y2.4 ; also on sheet 2 5 6 10 11 12 13 14 15 16 17 18 19 20 21 22 23 24 25 26 27 28 29 30 31
VDD_1V8: C79.1 J10.2 J11.1 L7.1 U6.D11(NVCC_GPIO1_2) U6.E11(NVCC_GPIO1_1) ; also on sheet 6 14 16 21 22 24
VDD_AON_3V3: J9.1 R51.2 R52.1
VDD_AON_ANA: C42.1 J11.3 U6.P12(VDD_AON_ANA)
VDD_AON_DIG: C47.1 U6.P11(VDD_AON_DIG)
VDD_AON_IN: C43.1 J9.2 R52.2 U6.U14(VDD_AON_IN)
VDD_BBSM_3V3: D8.A R40.2 R43.2 ; also on sheet 5 6 22
VDD_BBSM_ANA: C35.1 R47.2 U6.R12(VDD_BBSM_ANA)
VDD_BBSM_IN: C34.1 J6.2 R41.2 U6.U12(VDD_BBSM_IN)
VDD_COIN_3V: D9.A J7.1 R45.1
VDD_SOC_IN: C51.1 C53.1 C54.1 C55.1 C56.1 C59.1 J14.1 R59.1 R2161.2 U6.H8(VDD_SOC_2) U6.H9(VDD_SOC_3) U6.H10(VDD_SOC_1) U6.J8(VDD_SOC_5) U6.J9(VDD_SOC_6) U6.J10(VDD_SOC_4) U6.K10(VDD_SOC_7)
VDD_USB_1P8: C85.1 L6.2 L7.2 U6.B17(VDD_USB_1P8)
VDD_USB_3P3: C86.1 L8.2 U6.G12(VDD_USB_3P3)
VDD_VREFH: C46.1 J10.1 U6.H16(ADC_VREFH)
VDDA_1P0: C57.1 U6.N11(VDDA_1P0)
VDDA_ADC_3P3: C529.1 L3.2 R1340.2 U312.3(D2)
ADC_1V8_IN: C48.1 C49.1 C58.1 L4.2 R1339.1 U6.J13(VDDA_ADC_1P8) U6.M12(VDDA_1P8_IN)
AUD_INT: R2153.2 ; also on sheet 14
BT_DEV_WAKE: R1081.2 ; also on sheet 21
BT_PCM_BCLK: R1090.2 ; also on sheet 21
BT_PCM_RXD: U6.K13(GPIO_AD_20) ; also on sheet 21
BT_PCM_SYNC: U6.K14(GPIO_AD_23) ; also on sheet 21
BT_PCM_TXD: R1089.2 ; also on sheet 21
BT_RST#: R141.2 ; also on sheet 21
BT_UART10_CTS: R148.2 ; also on sheet 21
BT_UART10_RTS: R149.2 ; also on sheet 21
BT_UART10_RXD: R146.2 ; also on sheet 21
BT_UART10_TXD: R144.2 ; also on sheet 21
BT_WAKE_B_3V3: R143.2 ; also on sheet 21
CAN1_RX: R1343.2 ; also on sheet 20
CAN1_TX: R1342.2 ; also on sheet 20
CAN3_RX: U6.C8(GPIO_AON_03) ; also on sheet 20
CAN3_TX: R1344.2 ; also on sheet 20
CAN_STBY: U6.L15(GPIO_AD_29) ; also on sheet 20
CCM_CLKO1_25M: R1330.2 ; also on sheet 30 31
CCM_ENET_REF_CLK_25M: R1328.2 ; also on sheet 30 31
DC_GPIO1: R1083.2 ; also on sheet 24
DC_GPIO2: R1086.2 ; also on sheet 24
DC_I2S1_MCLK: R95.2 ; also on sheet 24
DC_I2S1_RX_BCLK: R98.2 ; also on sheet 24
DC_I2S1_RX_D0: R96.2 ; also on sheet 24
DC_I2S1_RX_SYNC: R99.2 ; also on sheet 24
DC_I2S1_TX_BCLK: R94.2 ; also on sheet 24
DC_I2S1_TX_D0: R92.2 ; also on sheet 24
DC_I2S1_TX_D1: R97.2 ; also on sheet 24
DC_I2S1_TX_SYNC: R93.2 ; also on sheet 24
DC_I2S4_MCLK: R125.2 ; also on sheet 24
DC_I2S4_RX_BCLK: R133.2 ; also on sheet 24
DC_I2S4_RX_D0: R134.2 ; also on sheet 24
DC_I2S4_RX_SYNC: R132.2 ; also on sheet 24
DC_I2S4_TX_BCLK: R127.2 ; also on sheet 24
DC_I2S4_TX_D0: R131.2 ; also on sheet 24
DC_I2S4_TX_SYNC: R129.2 ; also on sheet 24
DC_INT: R1085.2 ; also on sheet 24
DC_RESET: R1084.2 ; also on sheet 24
DCDC_1V8_OUT: J77.2 L6.1 R58.2
DMIC_CLK: R867.2 ; also on sheet 13
DMIC_DATA0: R868.2 ; also on sheet 13
DMIC_DATA1: R100.2 ; also on sheet 13
DMIC_DATA2: R101.2 ; also on sheet 13
DMIC_DATA3: R102.2 ; also on sheet 13
ECAT0_RST_B: R958.2 ; also on sheet 31
ECAT0_RXER: R960.2 ; also on sheet 31
ECAT1_RST_B: R1018.2 ; also on sheet 30
ECAT_LINK0: R2159.2 ; also on sheet 31
ECAT_LINK1: R2160.2 ; also on sheet 30
ENET0_CRS_DV: R234.2 R2606.1 ; also on sheet 31
ENET0_INT_B: U6.M13(GPIO_AD_24) ; also on sheet 31
ENET0_RST_B: U6.M15(GPIO_AD_25) ; also on sheet 31
ENET0_RXD0: R232.2 R2604.1 ; also on sheet 31
ENET0_RXD1: R233.2 R2605.1 ; also on sheet 31
ENET0_RXER: R235.2 R2607.1 ; also on sheet 31
ENET0_TX_REF_CLK: R231.2 R2603.1 ; also on sheet 31
ENET0_TXD0: R228.2 ; also on sheet 31
ENET0_TXD1: R229.2 ; also on sheet 31
ENET0_TXEN: R230.2 R2620.1 ; also on sheet 31
ENET1_INT_B: R2643.2 ; also on sheet 16
ENET1_RGMII_RX_EN: U6.B10(GPIO_B1_06) ; also on sheet 16
ENET1_RGMII_RXC: U6.A12(GPIO_B1_11) ; also on sheet 16
ENET1_RGMII_RXD0: U6.B13(GPIO_B1_04) ; also on sheet 16
ENET1_RGMII_RXD1: U6.B12(GPIO_B1_05) ; also on sheet 16
ENET1_RGMII_RXD2: U6.A15(GPIO_B1_09) ; also on sheet 16
ENET1_RGMII_RXD3: U6.A13(GPIO_B1_10) ; also on sheet 16
ENET1_RGMII_TX_EN: U6.E12(GPIO_B1_02) ; also on sheet 16
ENET1_RGMII_TXC: U6.A14(GPIO_B1_03) ; also on sheet 16
ENET1_RGMII_TXD0: U6.E13(GPIO_B1_00) ; also on sheet 16
ENET1_RGMII_TXD1: U6.C12(GPIO_B1_01) ; also on sheet 16
ENET1_RGMII_TXD2: U6.D13(GPIO_B1_07) ; also on sheet 16
ENET1_RGMII_TXD3: U6.B14(GPIO_B1_08) ; also on sheet 16
ENET1_RST_B: R2644.2 ; also on sheet 16
ENET2_INT_B: R128.2 R1087.2 ; also on sheet 17
ENET2_RGMII_RX_EN: R216.2 ; also on sheet 17
ENET2_RGMII_RXC: R219.2 ; also on sheet 17
ENET2_RGMII_RXD0: R217.2 ; also on sheet 17
ENET2_RGMII_RXD1: R218.2 ; also on sheet 17
ENET2_RGMII_RXD2: R220.2 ; also on sheet 17
ENET2_RGMII_RXD3: R221.2 ; also on sheet 17
ENET2_RGMII_TXD2: R223.2 ; also on sheet 17
ENET2_RGMII_TXD3: R222.2 ; also on sheet 17
ENET2_RST_B: R1018.1 U6.L16(GPIO_AD_28) ; also on sheet 17
ENET3_INT_B: R111.2 R2697.2 U418.4(Y)
ENET3_INT_B_3V3: U418.2(A) ; also on sheet 18
ENET3_MII_COL: R1232.2 ; also on sheet 31
ENET3_MII_CRS: R1231.2 ; also on sheet 31
ENET3_RST_B: R114.2 R2696.2 U417.2(A)
ENET3_RST_B_3V3: R2695.2 U417.4(Y) ; also on sheet 18
ENET4_CARD_DET_B: R2596.2 ; also on sheet 29
ENET4_CRS_DV: R250.2 R2614.1 ; also on sheet 30
ENET4_GPIO: R2597.2 ; also on sheet 29
ENET4_INT_B: R137.2 ; also on sheet 29 30
ENET4_RGMII_RX_EN: R2614.2 ; also on sheet 29
ENET4_RGMII_RXC: R2603.2 ; also on sheet 29
ENET4_RGMII_RXD0: R2612.2 ; also on sheet 29
ENET4_RGMII_RXD1: R2613.2 ; also on sheet 29
ENET4_RGMII_RXD2: R2605.2 ; also on sheet 29
ENET4_RGMII_RXD3: R2604.2 ; also on sheet 29
ENET4_RGMII_TX_EN: R2610.2 ; also on sheet 29
ENET4_RGMII_TXC: R2611.2 ; also on sheet 29
ENET4_RGMII_TXD0: R2608.2 ; also on sheet 29
ENET4_RGMII_TXD1: R2609.2 ; also on sheet 29
ENET4_RGMII_TXD2: R2607.2 ; also on sheet 29
ENET4_RGMII_TXD3: R2606.2 ; also on sheet 29
ENET4_RST_B: R138.2 ; also on sheet 29 30
ENET4_RXD0: R246.2 R2612.1 ; also on sheet 30
ENET4_RXD1: R248.2 R2613.1 ; also on sheet 30
ENET4_RXER: R252.2 R2615.1 ; also on sheet 30
ENET4_RXER_DC: R2615.2 ; also on sheet 29
ENET4_TX_REF_CLK: R244.2 R2611.1 ; also on sheet 30
ENET4_TXD0: R238.2 R2608.1 ; also on sheet 30
ENET4_TXD1: R240.2 R2609.1 ; also on sheet 30
ENET4_TXEN: R242.2 R2610.1 ; also on sheet 30
ENET4_TXER: R2620.2 ; also on sheet 29
EWM_OUT_B: R115.2 ; also on sheet 5 22
Flash_RST: R2158.2 ; also on sheet 22
FLASH_VCC: C78.1 C82.1 C909.1 R2696.1 R2697.1 U6.F9(NVCC_GPIO2_1) U6.F10(NVCC_GPIO2_2) U6.H12(NVCC_SD2_1) U6.H13(NVCC_SD2_2) U417.5(VCC) ; also on sheet 6 11 22
FlexSPI1_A_CLK: U6.A7(GPIO_B2_08) ; also on sheet 11
FlexSPI1_A_D0: U6.A10(GPIO_B2_10) ; also on sheet 11
FlexSPI1_A_D1: U6.B9(GPIO_B2_11) ; also on sheet 11
FlexSPI1_A_D2: U6.A8(GPIO_B2_12) ; also on sheet 11
FlexSPI1_A_D3: U6.B8(GPIO_B2_13) ; also on sheet 11
FlexSPI1_A_D4: R117.2 ; also on sheet 11
FlexSPI1_A_D5: R119.2 ; also on sheet 11
FlexSPI1_A_D6: R121.2 ; also on sheet 11
FlexSPI1_A_D7: R123.2 ; also on sheet 11
FlexSPI1_A_DQS: U6.A6(GPIO_B2_07) ; also on sheet 11
FlexSPI1_A_SS0: U6.D10(GPIO_B2_09) ; also on sheet 11
FlexSPI1_B_CLK: U6.E14(GPIO_SD_B2_07) ; also on sheet 11
FlexSPI1_B_D0: U6.F14(GPIO_SD_B2_08) ; also on sheet 11
FlexSPI1_B_D1: U6.F16(GPIO_SD_B2_09) ; also on sheet 11
FlexSPI1_B_D2: U6.G16(GPIO_SD_B2_10) ; also on sheet 11
FlexSPI1_B_D3: U6.F17(GPIO_SD_B2_11) ; also on sheet 11
FlexSPI1_B_D4: U6.H15(GPIO_SD_B2_00) ; also on sheet 11
FlexSPI1_B_D5: U6.H14(GPIO_SD_B2_01) ; also on sheet 11
FlexSPI1_B_D6: U6.G17(GPIO_SD_B2_02) ; also on sheet 11
FlexSPI1_B_D7: U6.G13(GPIO_SD_B2_03) ; also on sheet 11
FlexSPI1_B_DQS: R2157.2 ; also on sheet 11
FlexSPI1_B_SS0: U6.F15(GPIO_SD_B2_06) ; also on sheet 11
GPIO_AD_00: R867.1 U6.N12(GPIO_AD_00) ; also on sheet 27
GPIO_AD_01: R868.1 U6.R14(GPIO_AD_01) ; also on sheet 27
GPIO_AD_02: R100.1 U6.R13(GPIO_AD_02) ; also on sheet 27
GPIO_AD_03: R101.1 U6.R15(GPIO_AD_03) ; also on sheet 27
GPIO_AD_04: R102.1 U6.P15(GPIO_AD_04) ; also on sheet 11 27
GPIO_AD_05: R103.1 U6.P13(GPIO_AD_05) ; also on sheet 27
GPIO_AD_06: R104.1 U6.N13(GPIO_AD_06) ; also on sheet 26 27
GPIO_AD_07: R105.1 R135.1 U6.T17(GPIO_AD_07) ; also on sheet 27
GPIO_AD_08: R106.1 U6.T14(GPIO_AD_08) ; also on sheet 26 27
GPIO_AD_09: R107.1 U6.R16(GPIO_AD_09) ; also on sheet 27
GPIO_AD_10: R108.1 R136.1 U6.R17(GPIO_AD_10) ; also on sheet 27
GPIO_AD_11: R1053.1 U6.P16(GPIO_AD_11) ; also on sheet 27
GPIO_AD_12: R109.1 R137.1 U6.P17(GPIO_AD_12) ; also on sheet 27
GPIO_AD_13: R110.1 R138.1 U6.N15(GPIO_AD_13) ; also on sheet 27
GPIO_AD_14: R112.1 R139.1 U6.N14(GPIO_AD_14) ; also on sheet 27
GPIO_AD_15: R113.1 R140.1 R2158.1 U6.N16(GPIO_AD_15) ; also on sheet 26 27
GPIO_AD_16: R116.1 R141.1 R2159.1 U6.N17(GPIO_AD_16) ; also on sheet 27
GPIO_AD_17: R118.1 R142.1 R2160.1 U6.M17(GPIO_AD_17) ; also on sheet 27
GPIO_AD_18: R120.1 R143.1 U6.K16(GPIO_AD_18) ; also on sheet 26 27
GPIO_AD_19: R122.1 U6.L13(GPIO_AD_19) ; also on sheet 26 27
GPIO_AD_21: R1089.1 U6.K15(GPIO_AD_21) ; also on sheet 27
GPIO_AD_22: R1090.1 U6.K12(GPIO_AD_22) ; also on sheet 27
GPIO_AD_30: R1052.1 U6.L17(GPIO_AD_30) ; also on sheet 27
GPIO_AD_32: R124.1 R128.1 R144.1 U6.J17(GPIO_AD_32)
GPIO_AD_33: R126.1 R146.1 U6.J16(GPIO_AD_33) ; also on sheet 27
GPIO_AD_34: R148.1 R1042.1 U6.J15(GPIO_AD_34) ; also on sheet 27
GPIO_AD_35: R130.1 R149.1 U6.H17(GPIO_AD_35) ; also on sheet 27
GPIO_AON_00: U6.F8(GPIO_AON_00) ; also on sheet 22
GPIO_AON_01: U6.B7(GPIO_AON_01) ; also on sheet 22
GPIO_AON_02: U6.B6(GPIO_AON_02) ; also on sheet 22
GPIO_AON_08: R74.1 U6.B1(GPIO_AON_08) ; also on sheet 26 27
GPIO_AON_09: R76.1 U6.A5(GPIO_AON_09) ; also on sheet 26 27
GPIO_AON_15: R79.1 U6.B3(GPIO_AON_15) ; also on sheet 27
GPIO_AON_16: R80.1 U6.C5(GPIO_AON_16) ; also on sheet 27
GPIO_AON_17: R1079.1 R1086.1 U6.D6(GPIO_AON_17)
GPIO_AON_18: R1080.1 R1085.1 R1344.1 U6.E6(GPIO_AON_18)
GPIO_AON_19: R81.1 R1084.1 R1087.1 U6.D5(GPIO_AON_19)
GPIO_AON_20: R82.1 R1081.1 R1083.1 U6.E5(GPIO_AON_20)
GPIO_AON_21: R83.1 R92.1 U6.F6(GPIO_AON_21)
GPIO_AON_22: R84.1 R93.1 TP96.1(TP) U6.C3(GPIO_AON_22)
GPIO_AON_23: R85.1 R94.1 TP97.1(TP) U6.C2(GPIO_AON_23)
GPIO_AON_24: R86.1 R95.1 TP98.1(TP) U6.C1(GPIO_AON_24)
GPIO_AON_25: R87.1 R96.1 R97.1 TP99.1(TP) U6.D2(GPIO_AON_25)
GPIO_AON_26: R88.1 R98.1 TP100.1(TP) U6.C4(GPIO_AON_26)
GPIO_AON_27: R89.1 R99.1 TP101.1(TP) U6.D3(GPIO_AON_27)
GPIO_B1_12: R2639.1 R2643.1 U6.A11(GPIO_B1_12)
GPIO_B1_13: R2640.1 R2644.1 U6.B11(GPIO_B1_13)
GPIO_B2_00: R111.1 R125.1 R2641.1 U6.E9(GPIO_B2_00)
GPIO_B2_01: R114.1 R127.1 R958.1 R2642.1 U6.E10(GPIO_B2_01)
GPIO_B2_02: R115.1 R129.1 R1328.1 U6.C10(GPIO_B2_02)
GPIO_B2_03: R117.1 R131.1 U6.D9(GPIO_B2_03)
GPIO_B2_04: R119.1 R132.1 U6.C9(GPIO_B2_04)
GPIO_B2_05: R121.1 R133.1 U6.A9(GPIO_B2_05)
GPIO_B2_06: R123.1 R134.1 U6.E8(GPIO_B2_06)
GPIO_BUTTON: R2155.2 ; also on sheet 6
GPIO_EMC_B1_00: R151.1 R203.1 U6.H3(GPIO_EMC_B1_00)
GPIO_EMC_B1_00_P: R203.2 ; also on sheet 18
GPIO_EMC_B1_01: R152.1 R205.1 U6.H4(GPIO_EMC_B1_01)
GPIO_EMC_B1_01_P: R205.2 ; also on sheet 18
GPIO_EMC_B1_02: R153.1 R206.1 U6.K2(GPIO_EMC_B1_02)
GPIO_EMC_B1_02_P: R206.2 ; also on sheet 18
GPIO_EMC_B1_03: R154.1 R207.1 U6.G3(GPIO_EMC_B1_03)
GPIO_EMC_B1_03_P: R207.2 ; also on sheet 18
GPIO_EMC_B1_04: R155.1 R208.1 U6.J4(GPIO_EMC_B1_04)
GPIO_EMC_B1_04_P: R208.2 ; also on sheet 18
GPIO_EMC_B1_05: R156.1 R209.1 U6.H6(GPIO_EMC_B1_05)
GPIO_EMC_B1_05_P: R209.2 ; also on sheet 18
GPIO_EMC_B1_06: R157.1 R210.1 U6.K3(GPIO_EMC_B1_06)
GPIO_EMC_B1_06_P: R210.2 ; also on sheet 18
GPIO_EMC_B1_07: R158.1 R211.1 U6.M3(GPIO_EMC_B1_07)
GPIO_EMC_B1_07_P: R211.2 ; also on sheet 18
GPIO_EMC_B1_08: R159.1 R212.1 U6.H5(GPIO_EMC_B1_08)
GPIO_EMC_B1_08_P: R212.2 ; also on sheet 18
GPIO_EMC_B1_09: R160.1 R213.1 U6.E1(GPIO_EMC_B1_09)
GPIO_EMC_B1_09_P: R213.2 ; also on sheet 18
GPIO_EMC_B1_10: R161.1 R214.1 U6.E3(GPIO_EMC_B1_10)
GPIO_EMC_B1_10_P: R214.2 ; also on sheet 18
GPIO_EMC_B1_11: R162.1 R215.1 U6.F2(GPIO_EMC_B1_11)
GPIO_EMC_B1_11_P: R215.2 ; also on sheet 18
GPIO_EMC_B1_12: R959.1 R960.1 U6.G6(GPIO_EMC_B1_12)
GPIO_EMC_B1_13: R163.1 R216.1 U6.F3(GPIO_EMC_B1_13)
GPIO_EMC_B1_14: R1229.1 R1231.1 U6.G5(GPIO_EMC_B1_14)
GPIO_EMC_B1_15: R1230.1 R1232.1 U6.G2(GPIO_EMC_B1_15)
GPIO_EMC_B1_16: R164.1 R217.1 U6.H1(GPIO_EMC_B1_16)
GPIO_EMC_B1_17: R165.1 R218.1 U6.E2(GPIO_EMC_B1_17)
GPIO_EMC_B1_18: R166.1 U6.D1(GPIO_EMC_B1_18)
GPIO_EMC_B1_19: R167.1 U6.F4(GPIO_EMC_B1_19)
GPIO_EMC_B1_21: R168.1 R219.1 U6.K4(GPIO_EMC_B1_21)
GPIO_EMC_B1_22: R169.1 R220.1 U6.L3(GPIO_EMC_B1_22)
GPIO_EMC_B1_23: R170.1 R221.1 U6.F1(GPIO_EMC_B1_23)
GPIO_EMC_B1_24: R171.1 R222.1 U6.P2(GPIO_EMC_B1_24)
GPIO_EMC_B1_25: R172.1 R223.1 U6.N3(GPIO_EMC_B1_25)
GPIO_EMC_B1_26: R173.1 R224.1 U6.N4(GPIO_EMC_B1_26)
GPIO_EMC_B1_26_P: R224.2 ; also on sheet 17
GPIO_EMC_B1_27: R174.1 R225.1 U6.J3(GPIO_EMC_B1_27)
GPIO_EMC_B1_27_P: R225.2 ; also on sheet 17
GPIO_EMC_B1_28: R175.1 R226.1 U6.F5(GPIO_EMC_B1_28)
GPIO_EMC_B1_28_P: R226.2 ; also on sheet 17
GPIO_EMC_B1_29: R176.1 R227.1 U6.E4(GPIO_EMC_B1_29)
GPIO_EMC_B1_29_P: R227.2 ; also on sheet 17
GPIO_EMC_B1_30_P: R177.1 U6.H2(GPIO_EMC_B1_30) ; also on sheet 28
GPIO_EMC_B1_31_P: R178.1 U6.J2(GPIO_EMC_B1_31) ; also on sheet 28
GPIO_EMC_B1_32_P: R179.1 U6.J1(GPIO_EMC_B1_32) ; also on sheet 28
GPIO_EMC_B1_33_P: R180.1 U6.K1(GPIO_EMC_B1_33) ; also on sheet 28
GPIO_EMC_B1_34_P: R181.1 U6.L2(GPIO_EMC_B1_34) ; also on sheet 28
GPIO_EMC_B1_35_P: R182.1 U6.L1(GPIO_EMC_B1_35) ; also on sheet 28
GPIO_EMC_B1_36_P: R183.1 U6.M1(GPIO_EMC_B1_36) ; also on sheet 28
GPIO_EMC_B1_37_P: R184.1 U6.N1(GPIO_EMC_B1_37) ; also on sheet 28
GPIO_EMC_B1_38_P: R185.1 U6.M2(GPIO_EMC_B1_38) ; also on sheet 28
GPIO_EMC_B1_39_P: R186.1 U6.P1(GPIO_EMC_B1_39) ; also on sheet 28
GPIO_EMC_B1_40_P: R187.1 U6.N2(GPIO_EMC_B1_40) ; also on sheet 28
GPIO_EMC_B1_41_P: R188.1 U6.R1(GPIO_EMC_B1_41) ; also on sheet 28
GPIO_EMC_B2_02: R1329.1 R1330.1 U6.P5(GPIO_EMC_B2_02)
GPIO_EMC_B2_03: R2594.1 R2596.1 U6.T5(GPIO_EMC_B2_03)
GPIO_EMC_B2_04: R2595.1 R2597.1 U6.R3(GPIO_EMC_B2_04)
GPIO_EMC_B2_05: R189.1 R228.1 U6.T4(GPIO_EMC_B2_05)
GPIO_EMC_B2_06: R190.1 R229.1 U6.T6(GPIO_EMC_B2_06)
GPIO_EMC_B2_07: R191.1 R230.1 U6.T7(GPIO_EMC_B2_07)
GPIO_EMC_B2_08: R192.1 R231.1 U6.U4(GPIO_EMC_B2_08)
GPIO_EMC_B2_09: R193.1 R232.1 U6.U5(GPIO_EMC_B2_09)
GPIO_EMC_B2_10: R194.1 R233.1 U6.U6(GPIO_EMC_B2_10)
GPIO_EMC_B2_11: R195.1 R234.1 U6.P6(GPIO_EMC_B2_11)
GPIO_EMC_B2_12: R196.1 R235.1 U6.R5(GPIO_EMC_B2_12)
GPIO_EMC_B2_13: R198.1 R238.1 U6.R6(GPIO_EMC_B2_13)
GPIO_EMC_B2_14: R200.1 R240.1 U6.N8(GPIO_EMC_B2_14)
GPIO_EMC_B2_15: R201.1 R242.1 U6.R4(GPIO_EMC_B2_15)
GPIO_EMC_B2_16: R202.1 R244.1 U6.R7(GPIO_EMC_B2_16)
GPIO_EMC_B2_17: R204.1 R246.1 U6.U7(GPIO_EMC_B2_17)
GPIO_EMC_B2_18: R248.1 TP13.1(TP) U6.P8(GPIO_EMC_B2_18)
GPIO_EMC_B2_19: R250.1 U6.U8(GPIO_EMC_B2_19)
GPIO_EMC_B2_20: R252.1 U6.R8(GPIO_EMC_B2_20)
GPIO_SD_B1_00: R64.2 TP94.1(TP) U6.B16(GPIO_SD_B1_00) ; also on sheet 10 26 27
GPIO_SD_B1_01: TP95.1(TP) U6.D15(GPIO_SD_B1_01) ; also on sheet 10 26 27
GPIO_SD_B1_02: R65.2 U6.D14(GPIO_SD_B1_02) ; also on sheet 10 26 27
GPIO_SD_B1_03: U6.C15(GPIO_SD_B1_03) ; also on sheet 10 26 27
GPIO_SD_B1_04: U6.B15(GPIO_SD_B1_04) ; also on sheet 10
GPIO_SD_B1_05: U6.A16(GPIO_SD_B1_05) ; also on sheet 10
HP_DET_B: R2152.2 ; also on sheet 14
I3C2_PUR: R142.2 ; also on sheet 25
I3C2_SCL: R120.2 ; also on sheet 24 25 26 31
I3C2_SDA: R122.2 ; also on sheet 24 25 26 31
INT1_COMBO: R1079.2 ; also on sheet 26
INT2_COMBO: R1080.2 ; also on sheet 26
JTAG_nTRST: U6.B5(GPIO_AON_10) ; also on sheet 27
JTAG_TCK: U6.A2(GPIO_AON_13) ; also on sheet 23 27
JTAG_TDI: U6.A3(GPIO_AON_12) ; also on sheet 27
JTAG_TDO: U6.A4(GPIO_AON_11) ; also on sheet 23 27
JTAG_TMS: U6.B2(GPIO_AON_14) ; also on sheet 23 27
LPI2C2_SCL: R80.2 ; also on sheet 14 21 26 29
LPI2C2_SDA: R79.2 ; also on sheet 14 21 26 29
LPSPI1_PCS0: R2153.1 U6.C7(GPIO_AON_05) ; also on sheet 12
LPSPI1_SCK: R2152.1 R2155.1 U6.B4(GPIO_AON_04) ; also on sheet 12
LPSPI1_SDI: R1343.1 U6.C6(GPIO_AON_07) ; also on sheet 12
LPSPI1_SDO: R1342.1 U6.E7(GPIO_AON_06) ; also on sheet 12
LPSPI6_CLK: R2640.2 ; also on sheet 21
LPSPI6_CS: R2639.2 ; also on sheet 21
LPSPI6_SDI: R2641.2 ; also on sheet 21
LPSPI6_SDO: R2642.2 ; also on sheet 21
LPUART1_RXD: R76.2 ; also on sheet 23
LPUART1_TXD: R74.2 ; also on sheet 23
LPUART12_RXD: R82.2 ; also on sheet 2 23
LPUART12_TXD: R81.2 ; also on sheet 2 23
MCU_DCDC_IN: C60.1 C61.1 C62.1 J12.2 R53.1 R54.2 R56.1 U6.L7(DCDC_IN_Q) U6.M5(DCDC_IN_1) U6.M6(DCDC_IN_2) U6.M7(DCDC_IN_3) U6.M8(DCDC_IN_4)
NETC_ECAT_MDC: R1052.2 ; also on sheet 16 17 18 29 30 31
NETC_ECAT_MDIO: U6.K17(GPIO_AD_31) ; also on sheet 16 17 18 29 30 31
NVCC_BBSM: C39.1 J8.1 R42.1 R44.1 R47.1 U6.U11(NVCC_BBSM) ; also on sheet 6
NVCC_SD: R64.1 R65.1 R71.1 ; also on sheet 6
ONOFF: U6.U10(ONOFF) ; also on sheet 6
OTG1_DN: U6.E16(USB1_DN) ; also on sheet 19
OTG1_DP: U6.E17(USB1_DP) ; also on sheet 19
OTG2_DN: U6.C16(USB2_DN) ; also on sheet 19 21
OTG2_DP: U6.C17(USB2_DP) ; also on sheet 19 21
PMIC_ON_REQ: R44.2 U6.U9(PMIC_ON_REQ) ; also on sheet 5
POR_PIN_RST_B: C36.1 R42.2 U6.T10(POR_B) ; also on sheet 22 27
SAI1_MCLK: R86.2 ; also on sheet 14
SAI1_RX_BCLK: R88.2 ; also on sheet 14
SAI1_RX_SYNC: R89.2 ; also on sheet 14
SAI1_RXD[0]: R87.2 ; also on sheet 14
SAI1_TX_BCLK: R85.2 ; also on sheet 14
SAI1_TX_SYNC: R84.2 ; also on sheet 14
SAI1_TXD[0]: R83.2 ; also on sheet 14
SD1_CD_B: R140.2 ; also on sheet 10
SD1_VSELECT: R1042.2 ; also on sheet 6
SD_PWREN_B: R139.2 ; also on sheet 6
SEMC_A0: R160.2 ; also on sheet 28
SEMC_A1: R161.2 ; also on sheet 28
SEMC_A2: R162.2 ; also on sheet 28
SEMC_A3: R959.2 ; also on sheet 28
SEMC_A4: R163.2 ; also on sheet 28
SEMC_A5: R1229.2 ; also on sheet 28
SEMC_A6: R1230.2 ; also on sheet 28
SEMC_A7: R164.2 ; also on sheet 28
SEMC_A8: R165.2 ; also on sheet 28
SEMC_A9: R166.2 ; also on sheet 28
SEMC_A10: R170.2 ; also on sheet 28
SEMC_A11: R167.2 ; also on sheet 28
SEMC_A12: U6.G1(GPIO_EMC_B1_20) ; also on sheet 28
SEMC_BA0: R168.2 ; also on sheet 28
SEMC_BA1: R169.2 ; also on sheet 28
SEMC_CAS: R171.2 ; also on sheet 28
SEMC_CKE: R174.2 ; also on sheet 28
SEMC_CLK: R173.2 ; also on sheet 28
SEMC_CS0: R176.2 ; also on sheet 28
SEMC_CSX0: R188.2 ; also on sheet 28
SEMC_D0: R151.2 ; also on sheet 28
SEMC_D1: R152.2 ; also on sheet 28
SEMC_D2: R153.2 ; also on sheet 28
SEMC_D3: R154.2 ; also on sheet 28
SEMC_D4: R155.2 ; also on sheet 28
SEMC_D5: R156.2 ; also on sheet 28
SEMC_D6: R157.2 ; also on sheet 28
SEMC_D7: R158.2 ; also on sheet 28
SEMC_D8: R177.2 ; also on sheet 28
SEMC_D9: R178.2 ; also on sheet 28
SEMC_D10: R179.2 ; also on sheet 28
SEMC_D11: R180.2 ; also on sheet 28
SEMC_D12: R181.2 ; also on sheet 28
SEMC_D13: R182.2 ; also on sheet 28
SEMC_D14: R183.2 ; also on sheet 28
SEMC_D15: R184.2 ; also on sheet 28
SEMC_D16: U6.N5(GPIO_EMC_B2_00) ; also on sheet 28
SEMC_D17: U6.R2(GPIO_EMC_B2_01) ; also on sheet 28
SEMC_D18: R1329.2 ; also on sheet 28
SEMC_D19: R2594.2 ; also on sheet 28
SEMC_D20: R2595.2 ; also on sheet 28
SEMC_D21: R189.2 ; also on sheet 28
SEMC_D22: R190.2 ; also on sheet 28
SEMC_D23: R191.2 ; also on sheet 28
SEMC_D24: R193.2 ; also on sheet 28
SEMC_D25: R194.2 ; also on sheet 28
SEMC_D26: R195.2 ; also on sheet 28
SEMC_D27: R196.2 ; also on sheet 28
SEMC_D28: R198.2 ; also on sheet 28
SEMC_D29: R200.2 ; also on sheet 28
SEMC_D30: R201.2 ; also on sheet 28
SEMC_D31: R202.2 ; also on sheet 28
SEMC_DM0: R159.2 ; also on sheet 28
SEMC_DM1: R185.2 ; also on sheet 28
SEMC_DM2: R192.2 ; also on sheet 28
SEMC_DM3: R204.2 ; also on sheet 28
SEMC_RAS: R172.2 ; also on sheet 28
SEMC_RDY: R187.2 ; also on sheet 28
SEMC_WE: R175.2 ; also on sheet 28
SENSOR_3V3: C76.1 C80.1 C81.1 C83.1 C84.1 C90.1 C91.1 C910.1 J12.1 L8.1 R43.1 R51.1 R54.1 R1338.1 R1340.1 R2695.1 U6.F7(NVCC_AON) U6.J5(NVCC_EMC1_1) U6.J6(NVCC_EMC1_2) U6.K5(NVCC_EMC1_3) U6.L12(NVCC_GPIO_AD_1) U6.M11(NVCC_GPIO_AD_2) U6.N6(NVCC_EMC2_2) U6.N7(NVCC_EMC2_1) U312.4(S2) U418.5(VCC) ; also on sheet 2 5 6 10 11 12 13 14 15 16 17 18 19 20 21 22 23 24 25 26 27 28 29 30 31
SINC2_EMBIT: R126.2 ; also on sheet 25
SINC2_EMCLK: R124.2 ; also on sheet 25
SINC2_MOD_CLK: R130.2 ; also on sheet 25
SPDIF_EXT_CLK: R112.2 ; also on sheet 15
SPDIF_IN: R113.2 ; also on sheet 15
SPDIF_LOCK: R109.2 ; also on sheet 15
SPDIF_OUT: R116.2 ; also on sheet 15
SPDIF_SR_CLK: R110.2 ; also on sheet 15
USB_OTG1_ID: R107.2 ; also on sheet 19
USB_OTG1_OC: R1053.2 ; also on sheet 19
USB_OTG1_PWR: R108.2 ; also on sheet 19
USB_OTG2_ID: R106.2 ; also on sheet 19
USB_OTG2_OC: R104.2 ; also on sheet 19
USB_OTG2_PWR: R105.2 ; also on sheet 19
USER_LED_CTL1: U6.M16(GPIO_AD_27) ; also on sheet 6
USER_LED_CTL2: U6.M14(GPIO_AD_26) ; also on sheet 6
VLDO_3V3: R40.1 ; also on sheet 6
WAKEUP: U6.T8(WAKEUP) ; also on sheet 6
WIFI_RST_B: R135.2 ; also on sheet 21
WIFI_WAKE_B_3V3: R136.2 ; also on sheet 21
WL_DEV_WAKE: R103.2 ; also on sheet 21
WL_RST#: R118.2 ; also on sheet 21
N100526107: TP12.1(TP) U6.G15(GPIO_SD_B2_04)
N100526140: C77.1 R71.2 U6.C13(NVCC_SD1)
N101209734: D18.C J8.4 U6.P10(GPIO_BBSM_01)
N101209737: D19.C J8.3 U6.R10(GPIO_BBSM_00)
N101209778: D8.C D9.C J6.1 R41.1 R45.2
N101209809: C37.1 U6.T13(RTC_XTALI) Y1.1
N101209834: C38.1 U6.U13(RTC_XTALO) Y1.2
N101209892: TP8.1(TP) U6.T9(PMIC_STBY_REQ)
N101210175: C44.1 C45.1 L3.1 U6.J14(VDDA_ADC_3P3)
N101210568: D10.C J8.12 U6.R11(GPIO_BBSM_09)
N101210571: D12.C J8.10 U6.R9(GPIO_BBSM_07)
N101210574: D11.C J8.11 U6.N9(GPIO_BBSM_08)
N101210577: D13.C J8.9 U6.M9(GPIO_BBSM_06)
N101210580: D14.C J8.8 U6.P9(GPIO_BBSM_05)
N101210583: D15.C J8.7 U6.N10(GPIO_BBSM_04)
N101210586: D16.C J8.6 U6.M10(GPIO_BBSM_03)
N101210589: D17.C J8.5 U6.L9(GPIO_BBSM_02)
N101211681: R2161.1 U6.L8(DCDC_SENSE)
N101211864: L5.1 U6.T1(DCDC_LP_1) U6.T2(DCDC_LP_2) U6.T3(DCDC_LP_3) U6.U2(DCDC_LP_5) U6.U3(DCDC_LP_4)
N101211874: C68.1 C69.1 C70.1 C71.1 J14.2 L5.2 R59.2
N101211894: C64.1 R56.2 R57.1 U6.L5(DCDC_PSWITCH)
N101213128: TP11.1(TP) U6.T15(CLK1_N)
N101213130: TP10.1(TP) U6.U15(CLK1_P)
N101213146: C73.1 D20.C TP9.1(TP) U6.J12(DAC_OUT)
N101224368: C88.1 R186.2
N101343693: C74.1 R62.1 U6.U16(XTALI) Y2.3
N101346492: C75.1 R62.2 U6.T16(XTALO) Y2.1
N102544921: J11.2 L4.1
N103596184: C63.1 R53.2 R55.1 U6.L6(DCDC_MODE)
N103598440: C65.1 C66.1 C72.1 J77.1 R58.1 U6.M4(DCDC_1P8)
N106014504: C530.1 R1339.2 U312.2(G1)
N106014760: R1338.2 U312.5(G2) U312.6(D1)
N106348035: R2157.1 U6.E15(GPIO_SD_B2_05)

Not connected (* = marked no-connect by the designer): U417 1(NC)*; U418 1(NC)*

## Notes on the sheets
sheet 7
- Default: 1-2
- U12
- R12
- BATTERY SUPPLY
- ESD Damage Protection
- U11
- 1.8 V I/O
- Internal VREF->J10 OPEN
  External VREF->J10 1-2
- Default: 1-2
- J14
- U14
- Default: OPEN
- Default: 2-3
- P12
- H16
- P11
- J13
- M12
- N11
- J8
- H8
- H10
- H9
- J10
- Default: 1-2
- L8
- M5
- M7
- Default: 1-2
- Default: 1-2
- M4
- NXP USE ONLY
- ESR<=60OHM, +-20PPM, CL=8PF,-30~85C
sheet 8
- F7
- CCM.CLKO1
- CCM.CLKO2
- C13
- H12/13
- CCMOBS1
- Floating FlexSPI_DQS PIN for QSPI Flash RW @133MHz
  (R2157 should be placed close to MCU pin )
- CCMOBS2
- OBSERV1
- OBSERV2
- OBSERV3
- OBSERV4
- L12
- M11
- D11/E11
- F9/F10
sheet 9
- J5
- J6
- B17
- SEMC_DQS PIN need
  floating for SDRAM RW @200MHz
- G12
- D17
- D16
- SEMC_DQS
- N6/N7
- ENET2&ENET3 Multiplex
- SEMC_DQS4
- Note about minimizing stubs on ENET&OCRAM signals.
- ENET0&ENET4 RMII Multiplex
- OCTRAM Multiplex
- ENET4 RGMII DC Multiplex
